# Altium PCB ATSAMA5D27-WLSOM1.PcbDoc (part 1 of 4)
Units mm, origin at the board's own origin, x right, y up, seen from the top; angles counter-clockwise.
Board outline 40.8 x 40.8 mm, 6 copper layers (L1 - Top, L2 - GND, L3 - Signal, L4 - Signal, L5 - PWR, L6 - Bottom), stack 1.144 mm thick; 196 components, 221 nets, 1038 pads, 713 vias.
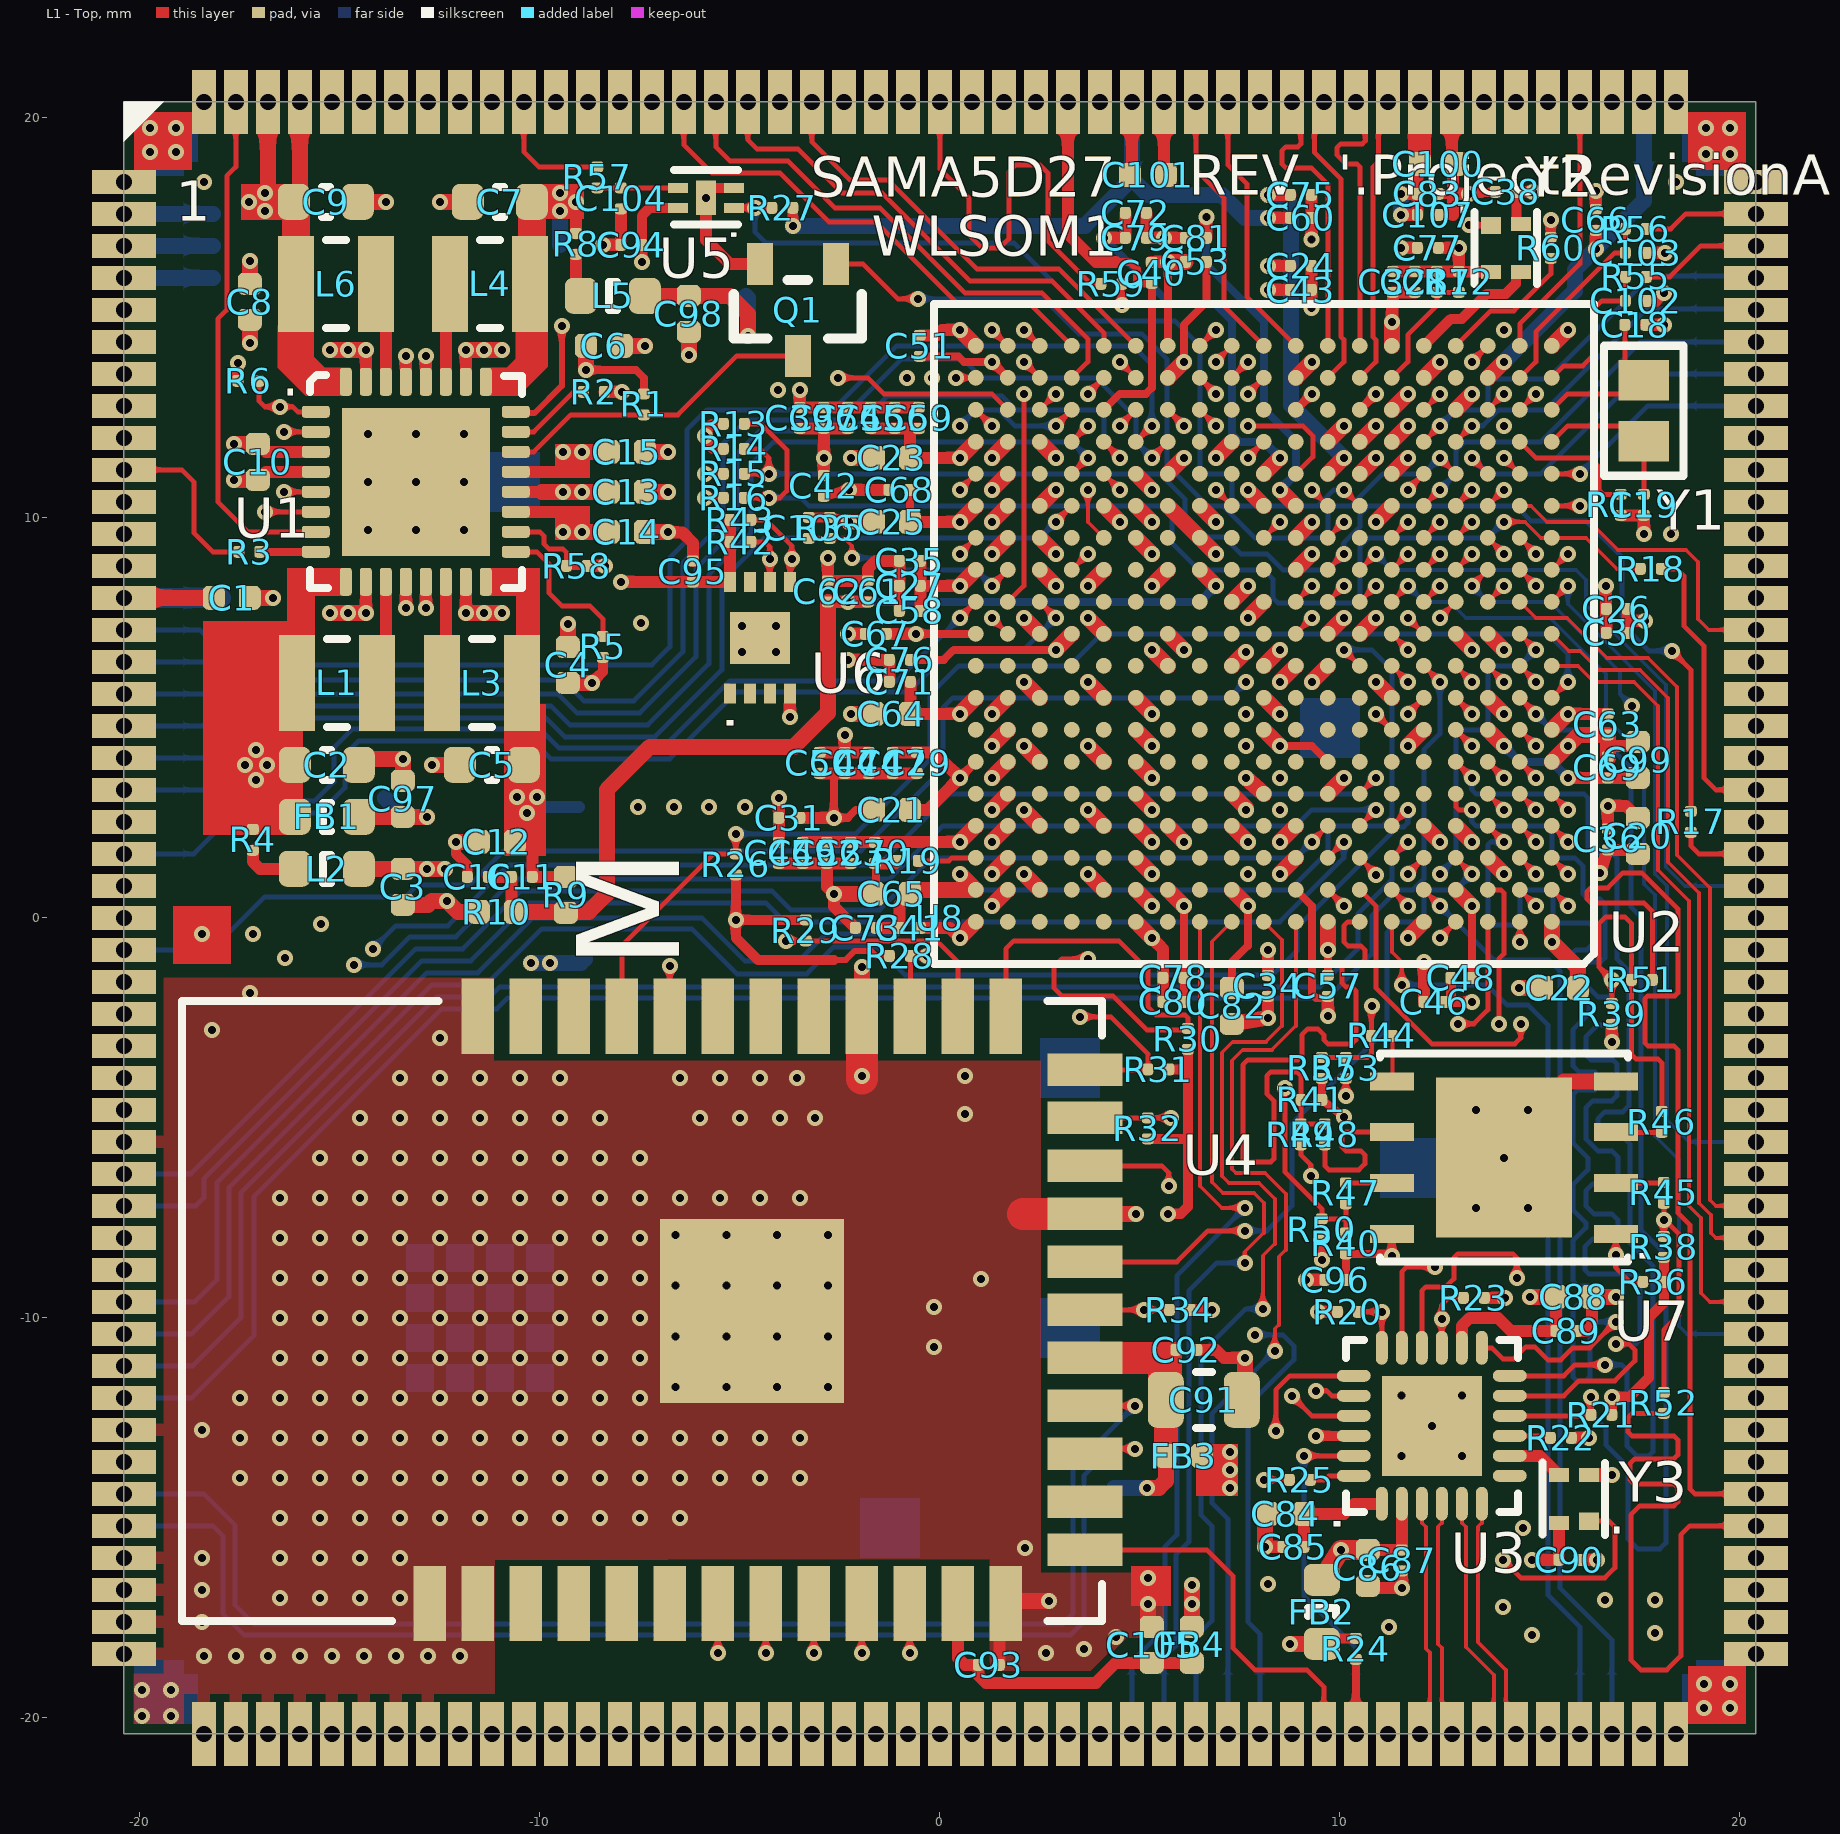
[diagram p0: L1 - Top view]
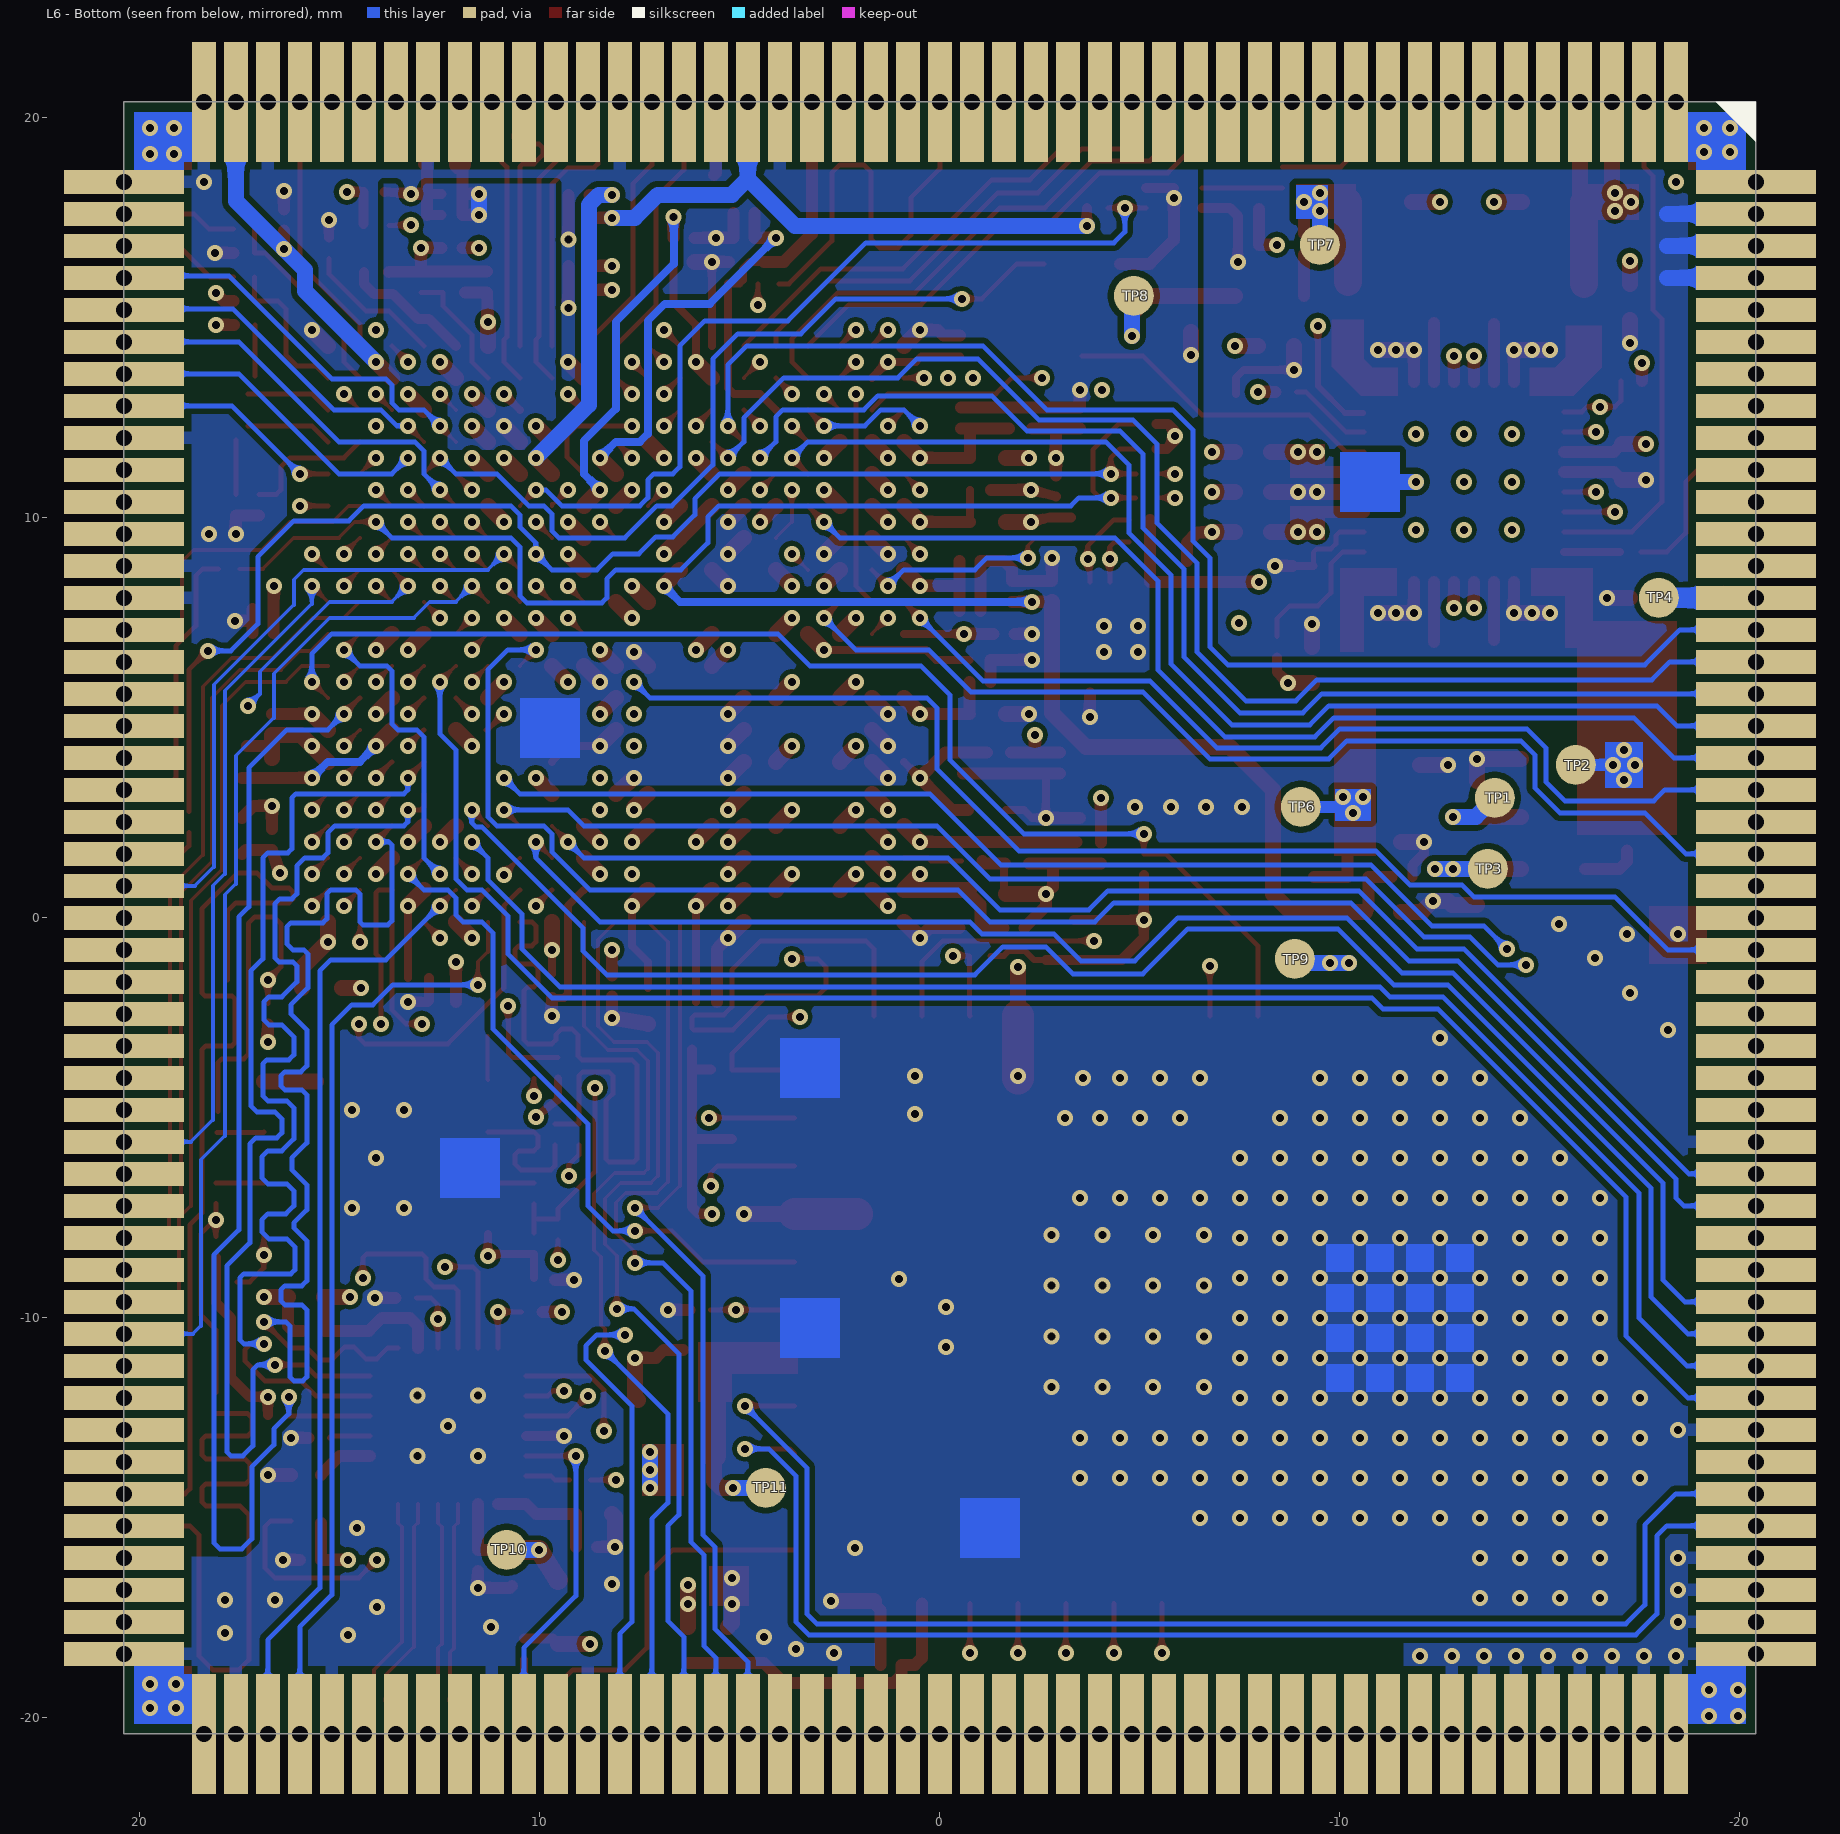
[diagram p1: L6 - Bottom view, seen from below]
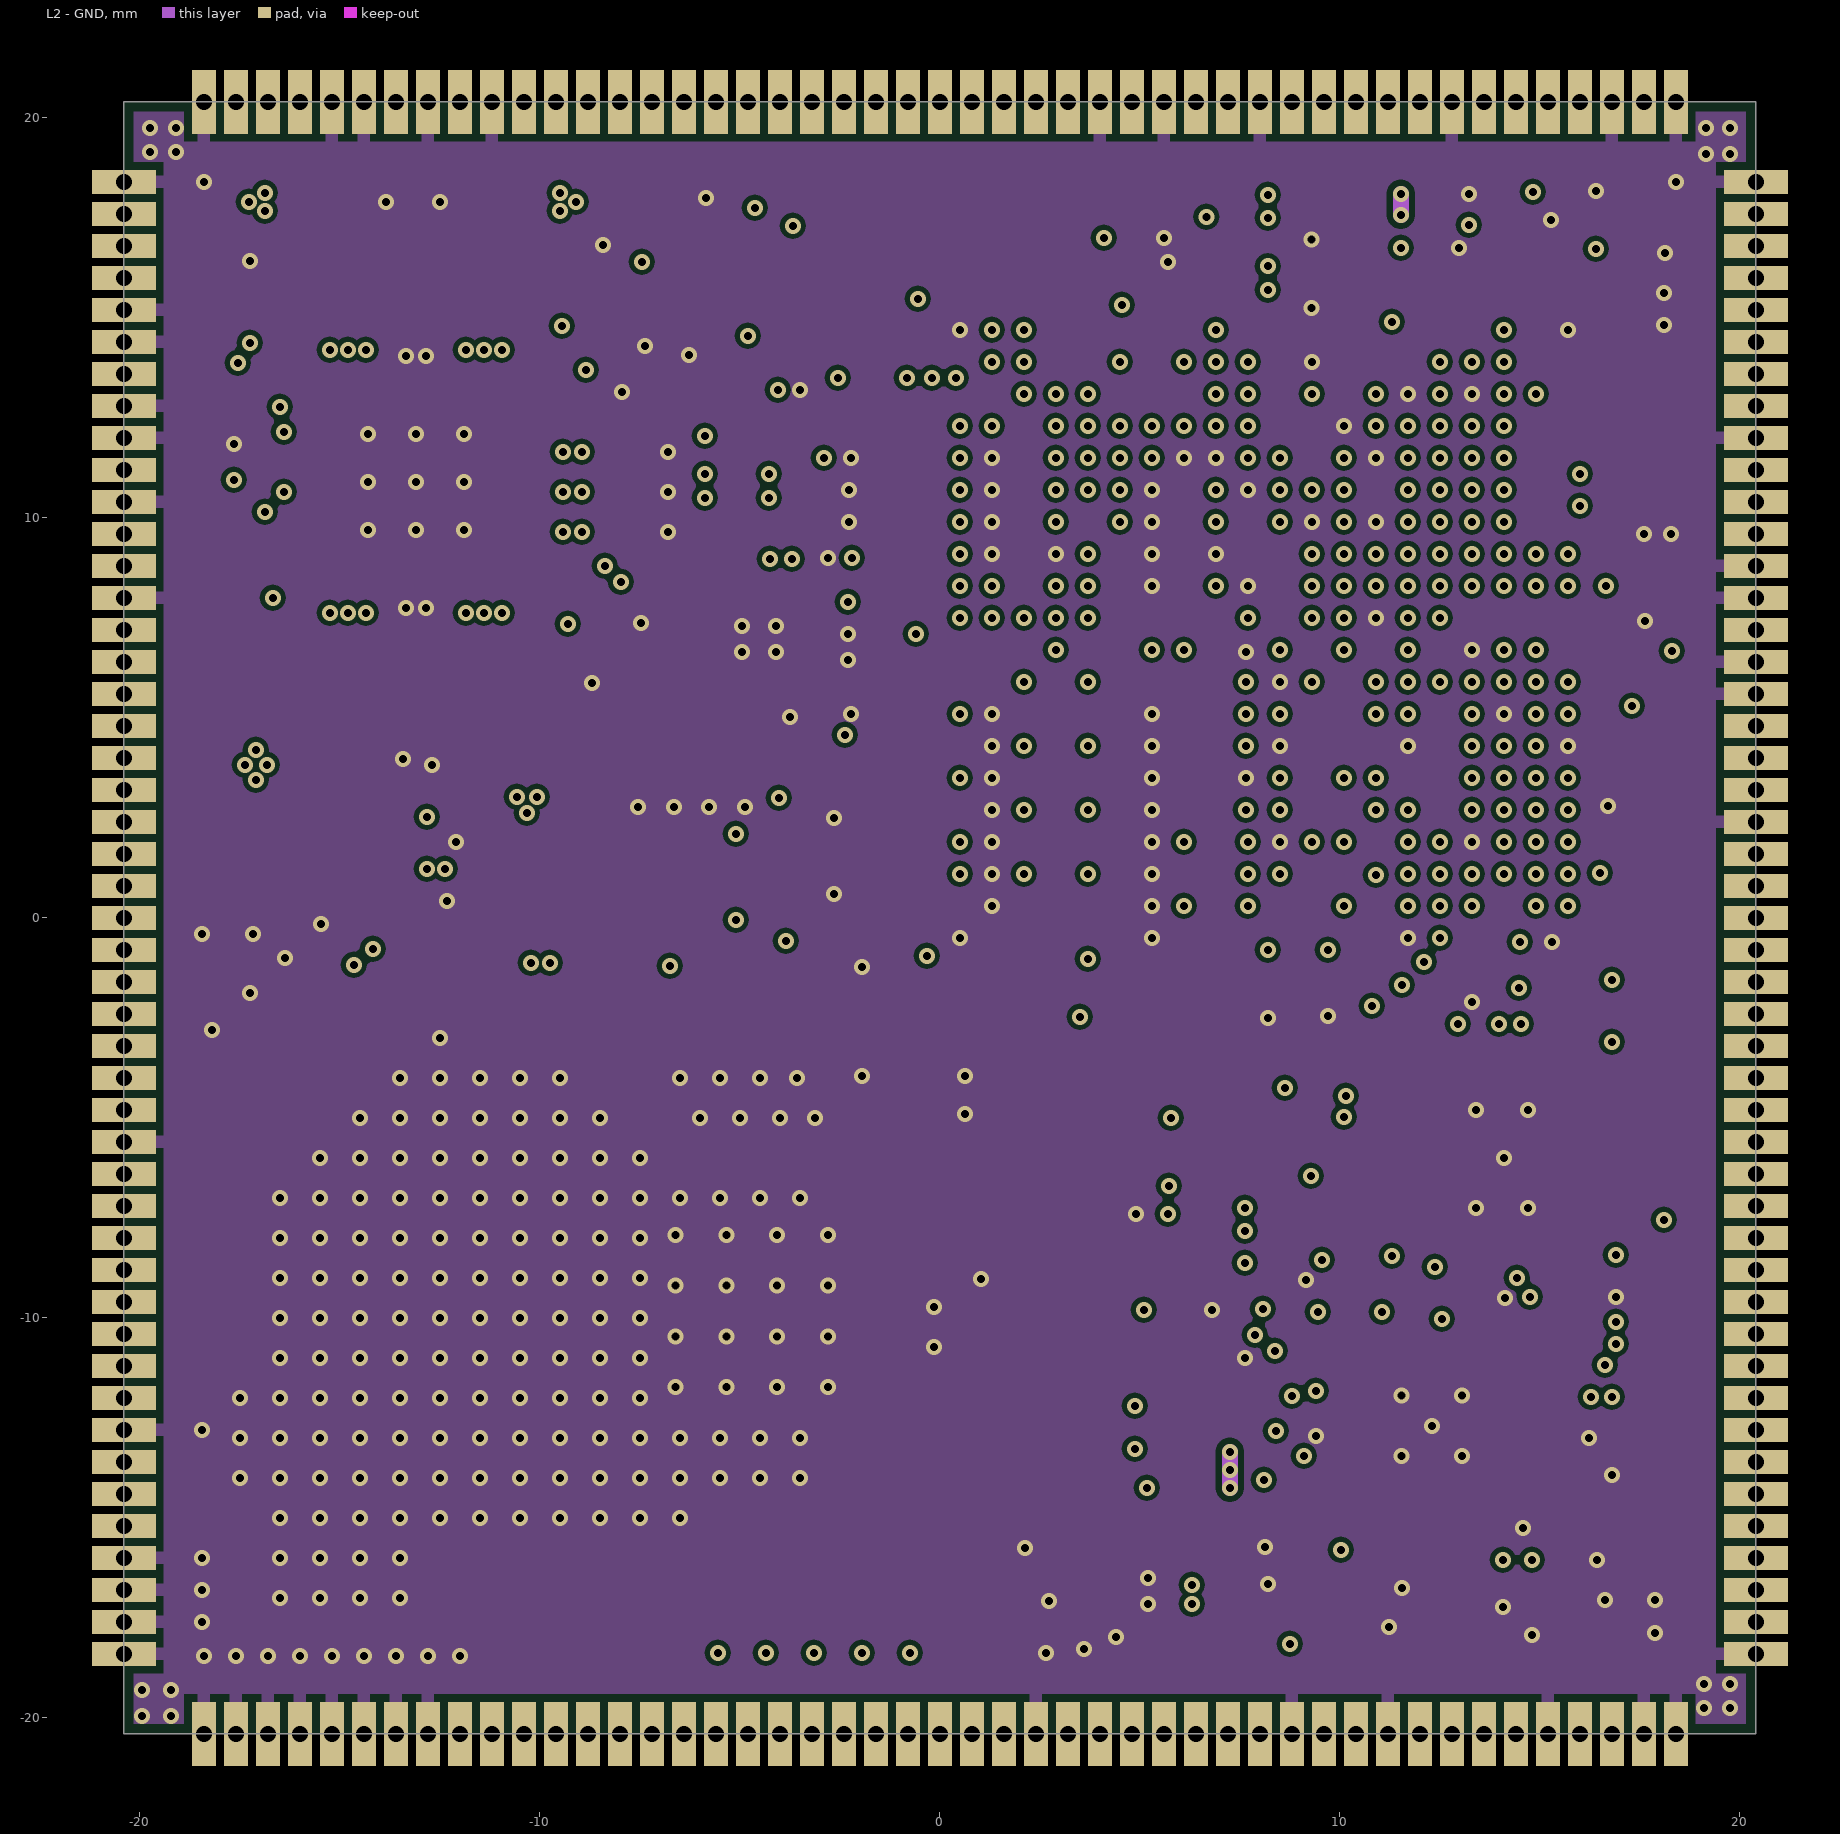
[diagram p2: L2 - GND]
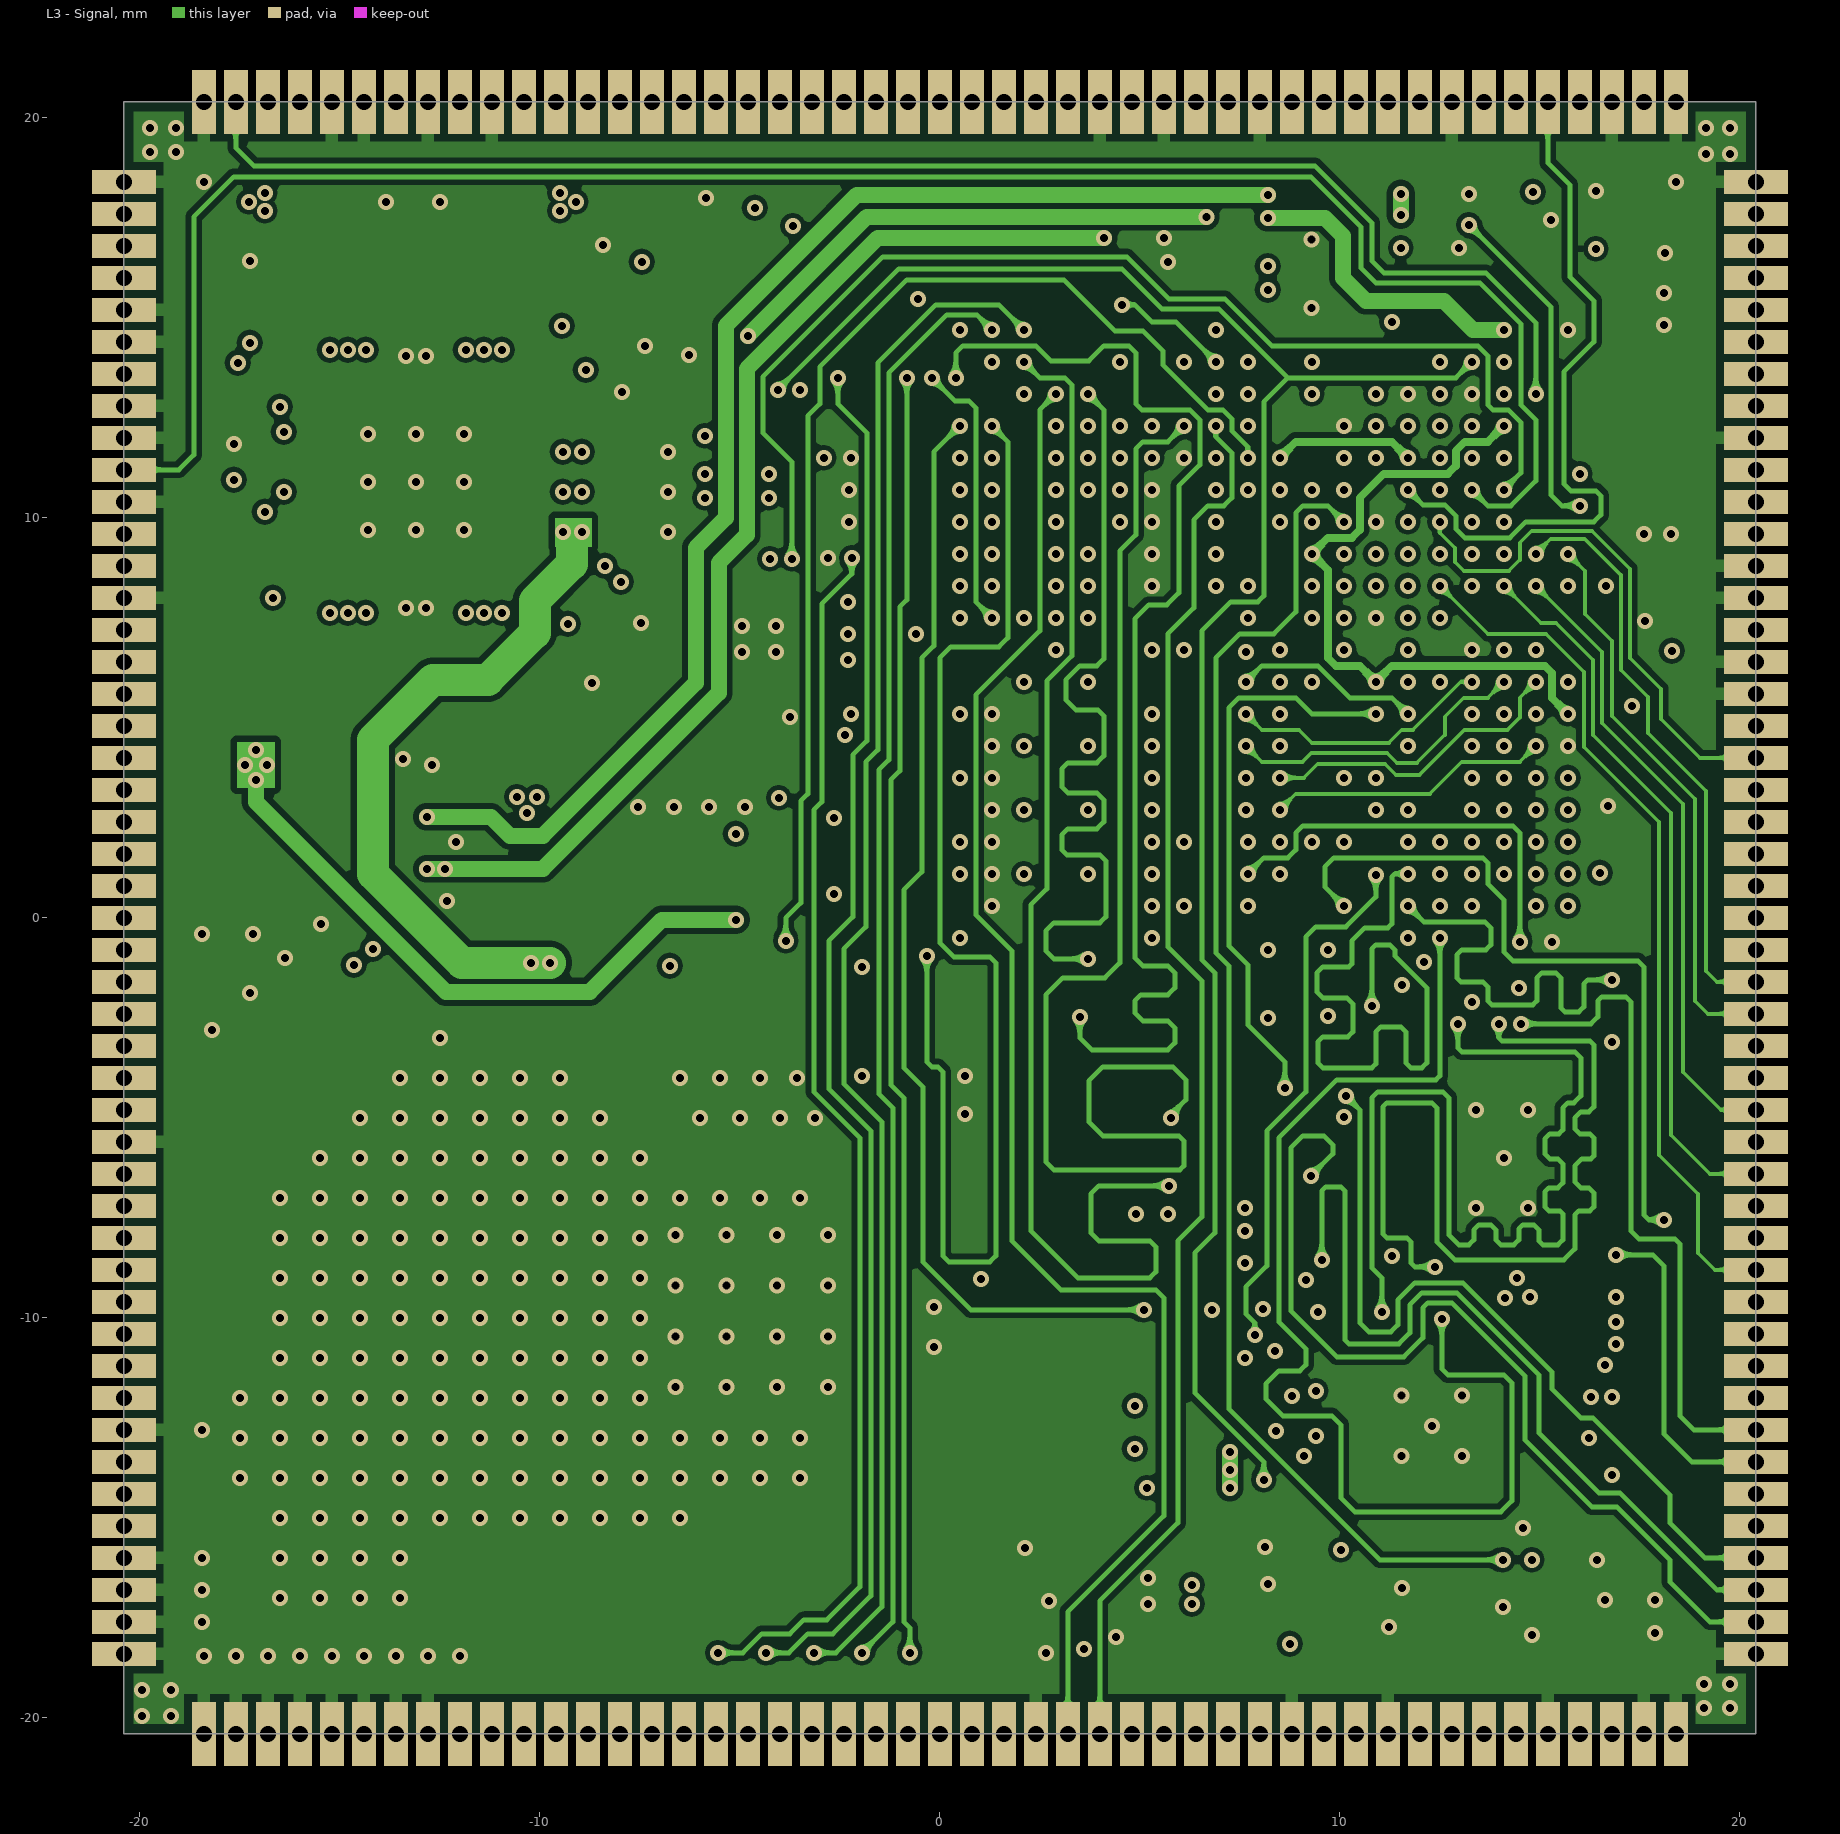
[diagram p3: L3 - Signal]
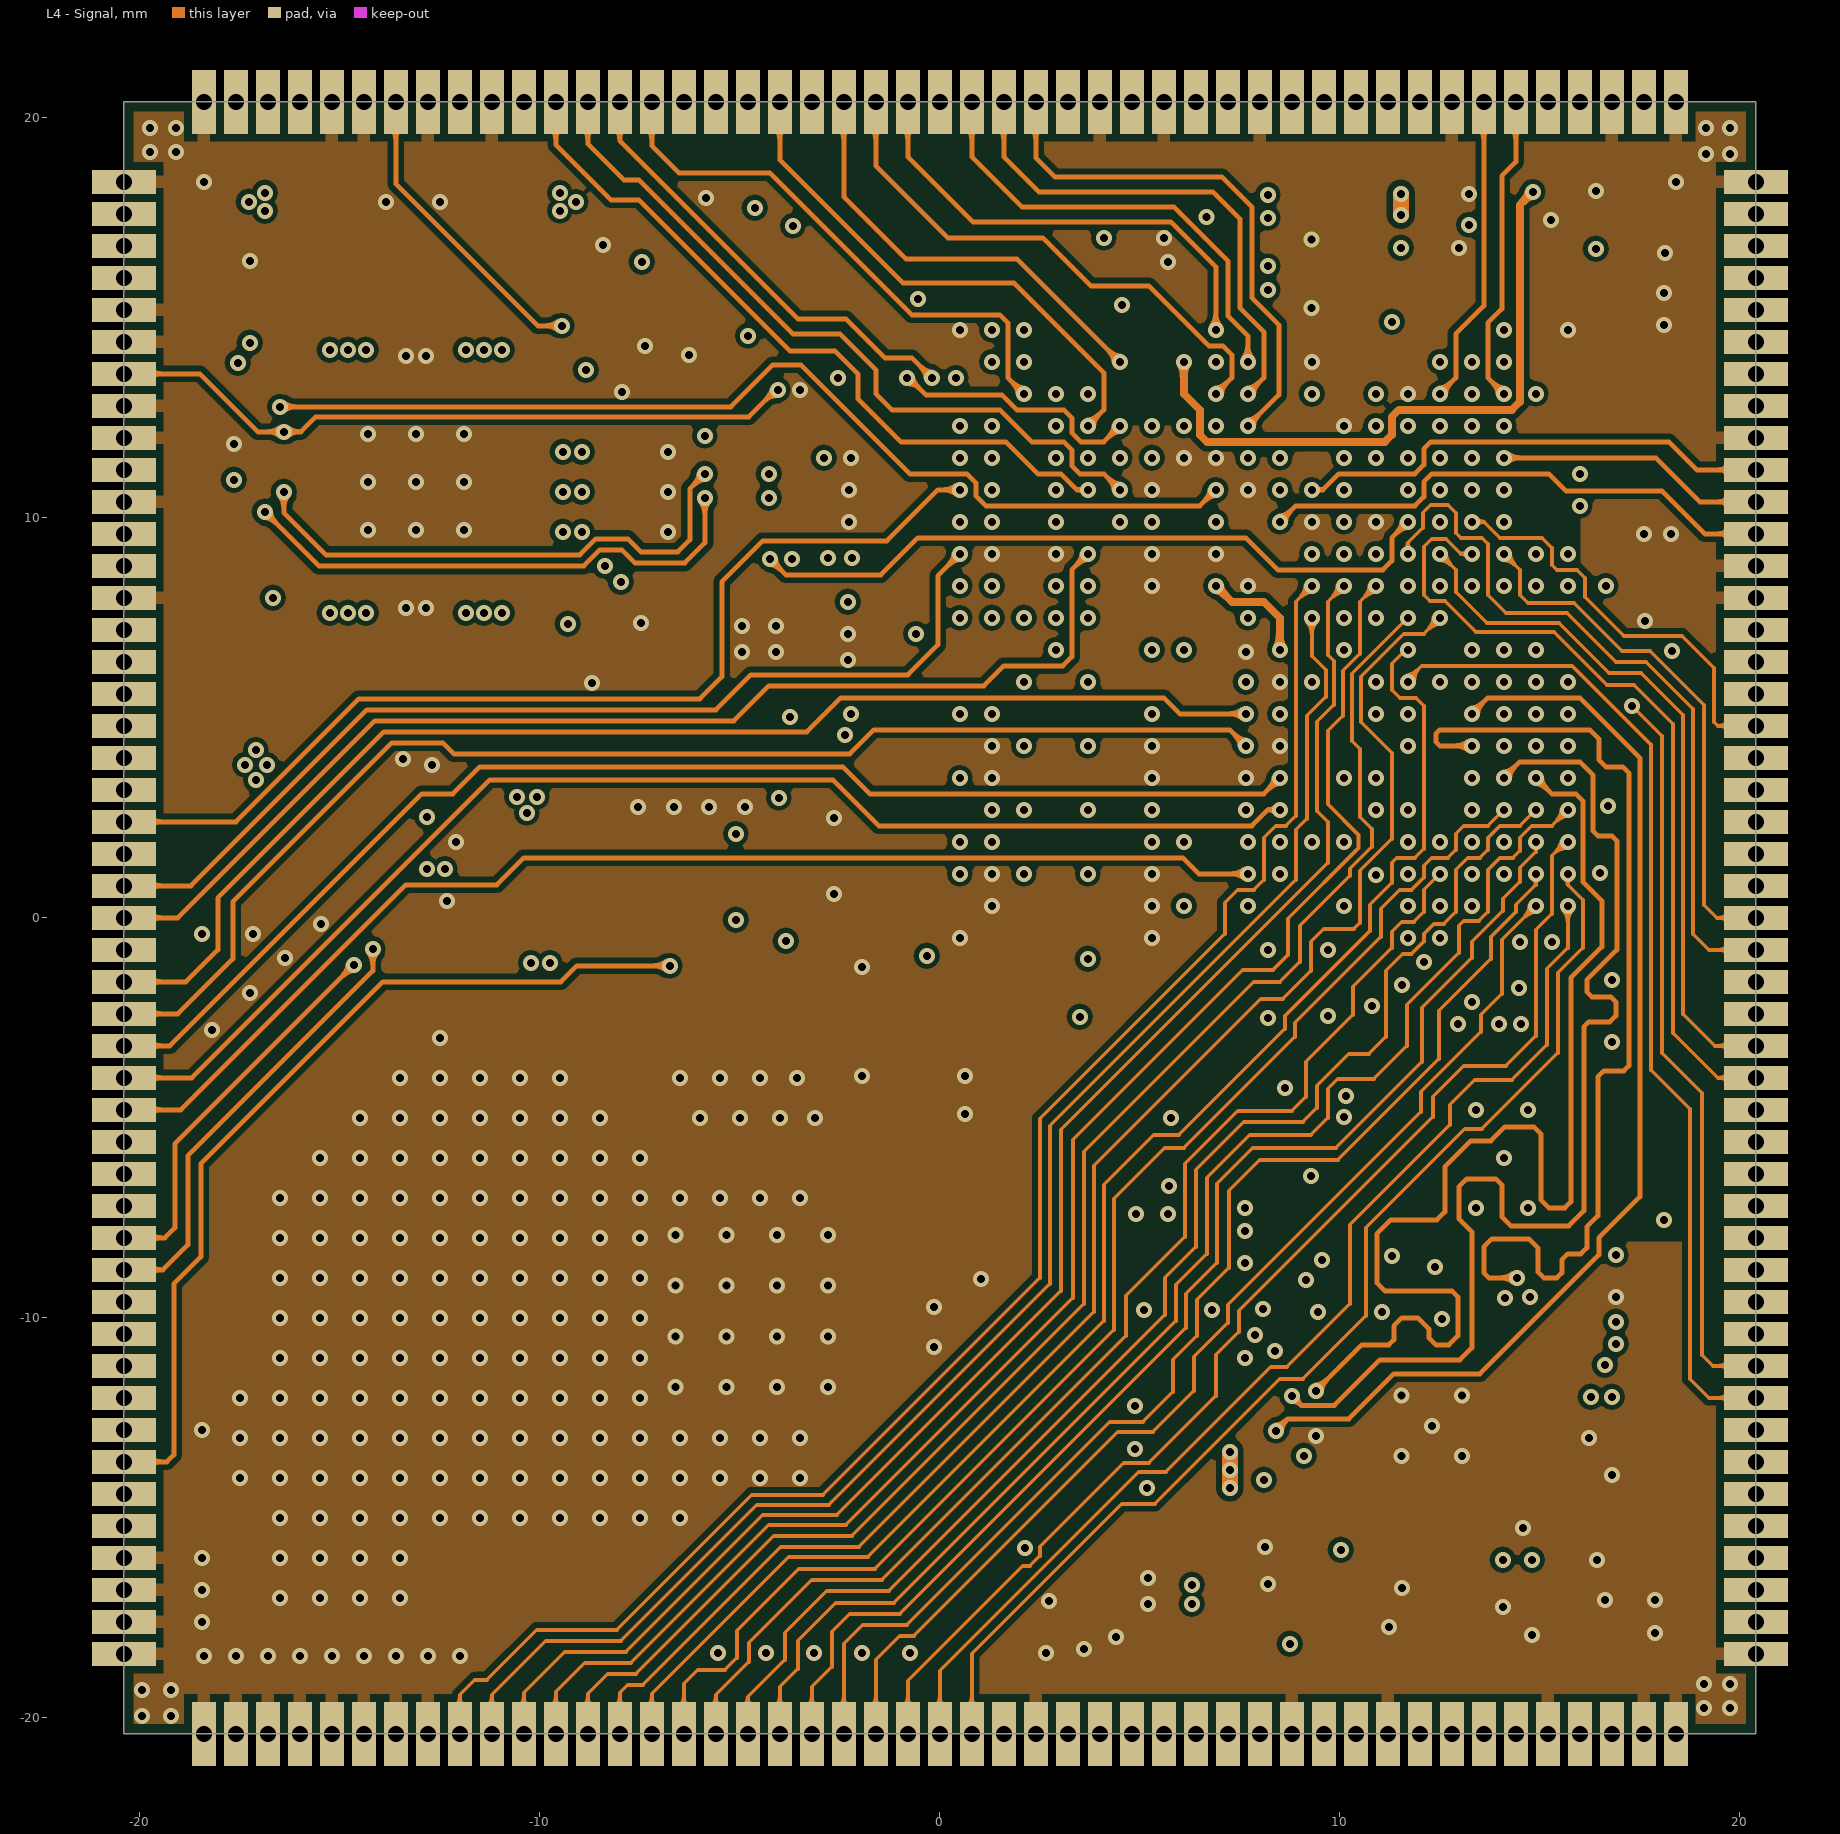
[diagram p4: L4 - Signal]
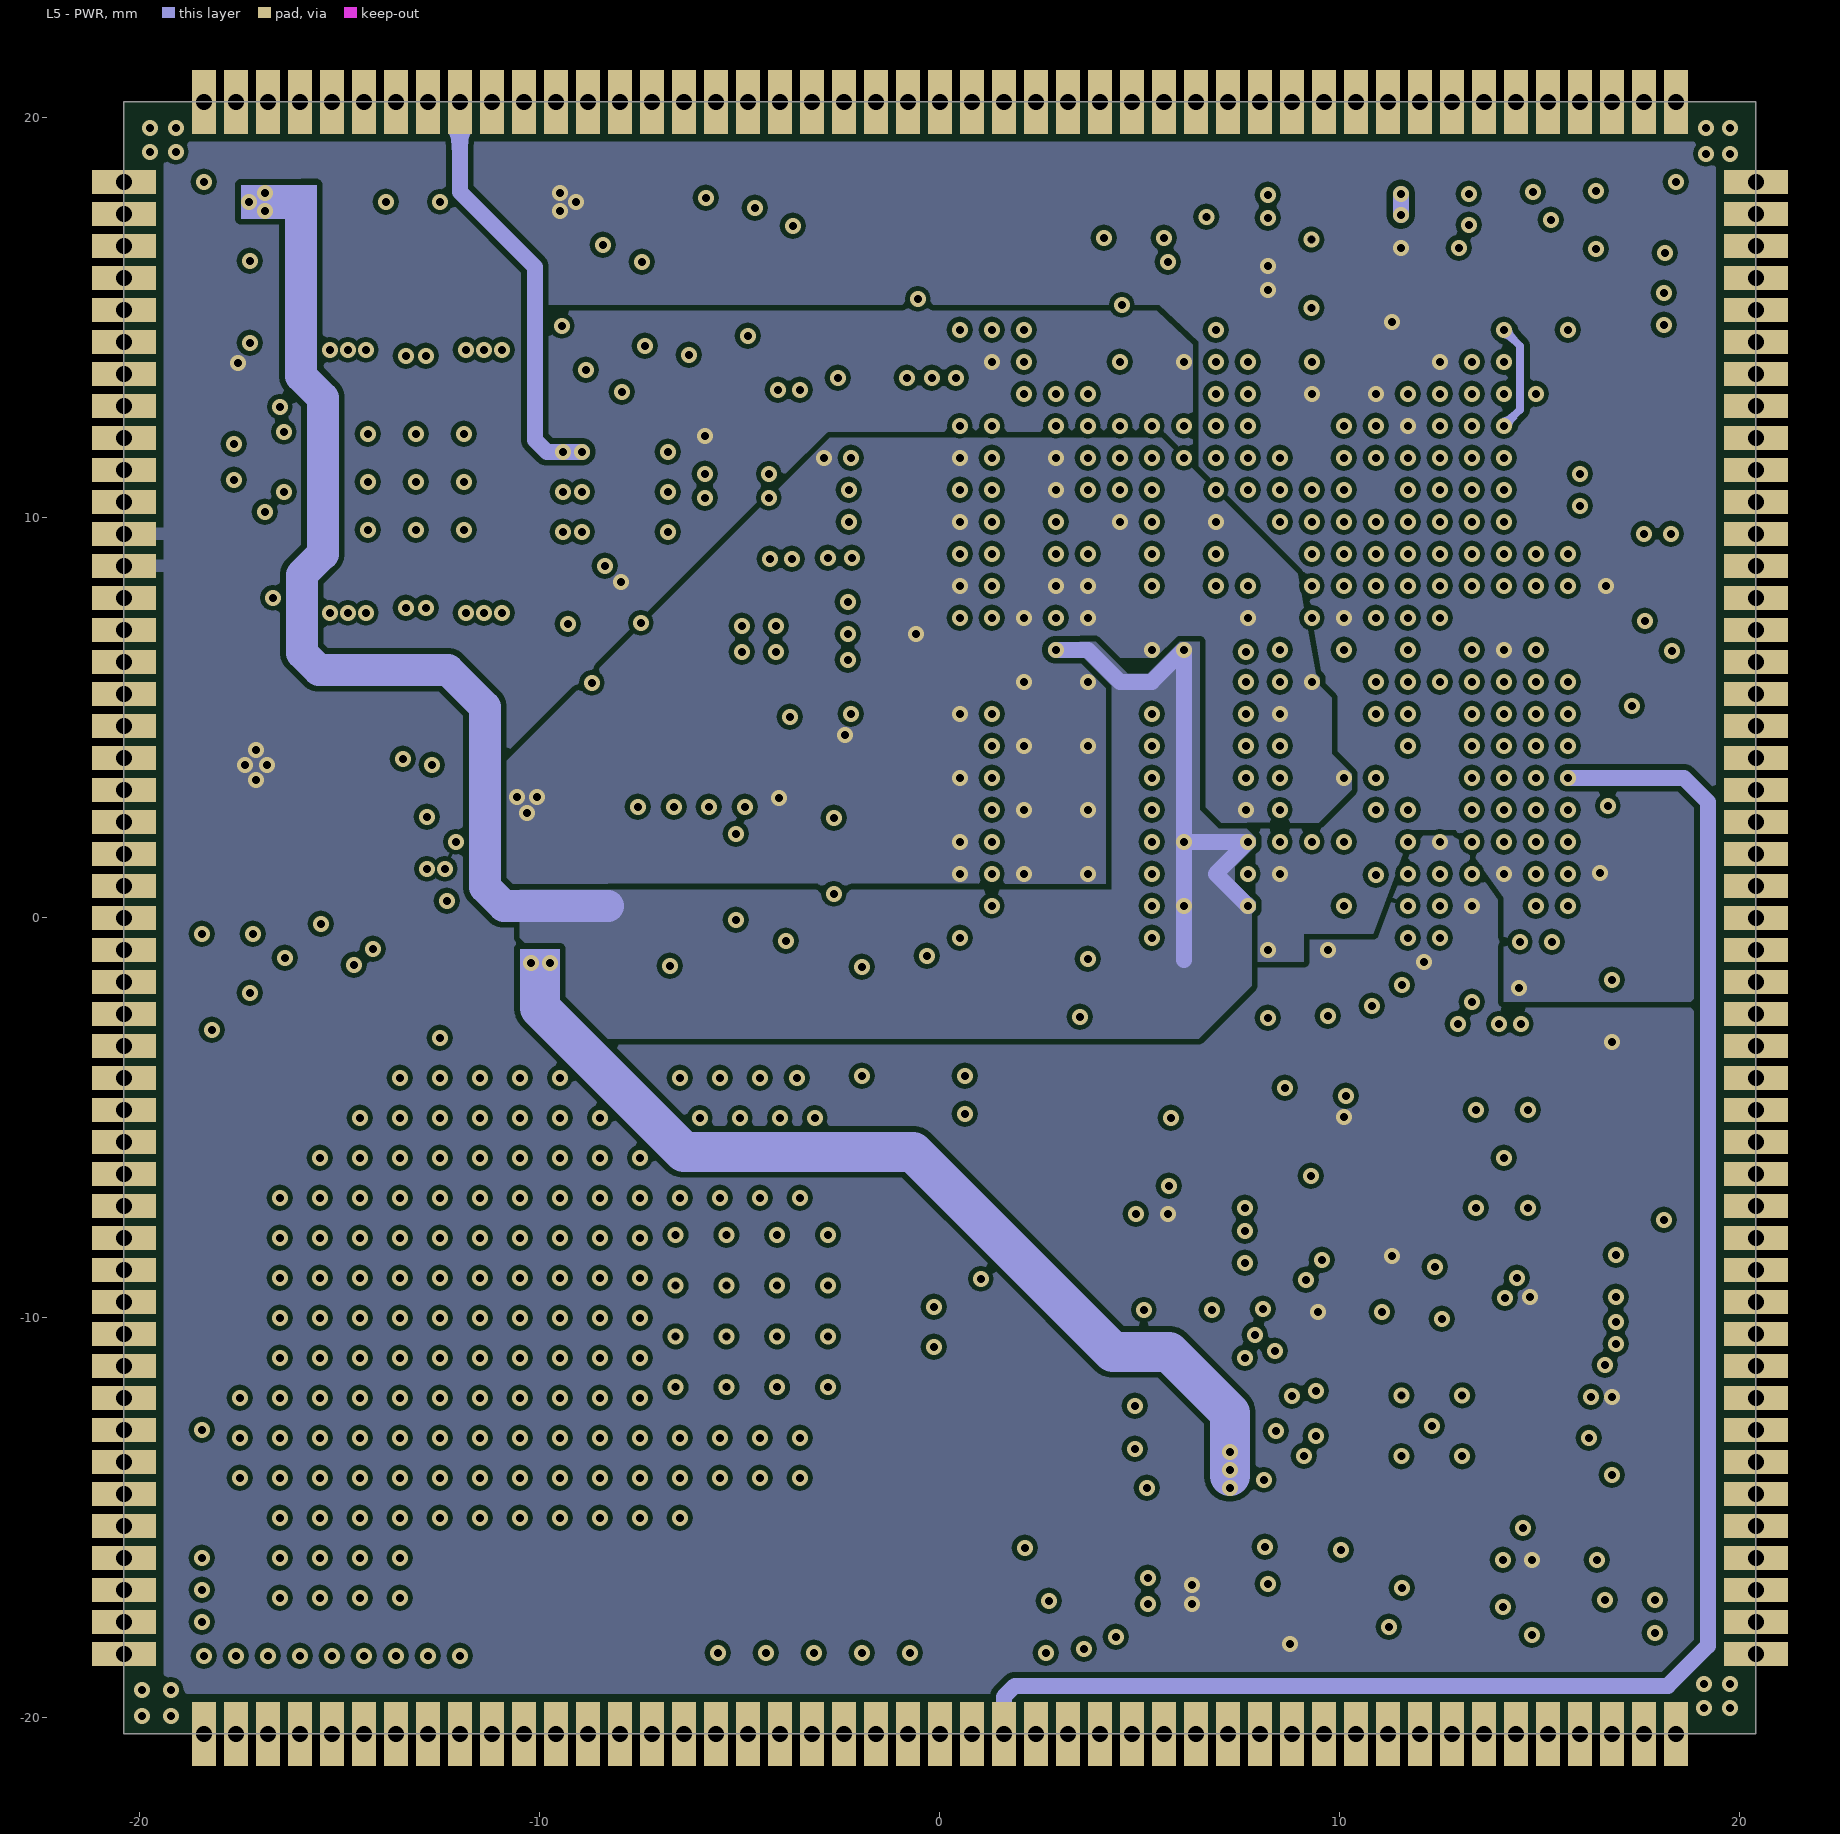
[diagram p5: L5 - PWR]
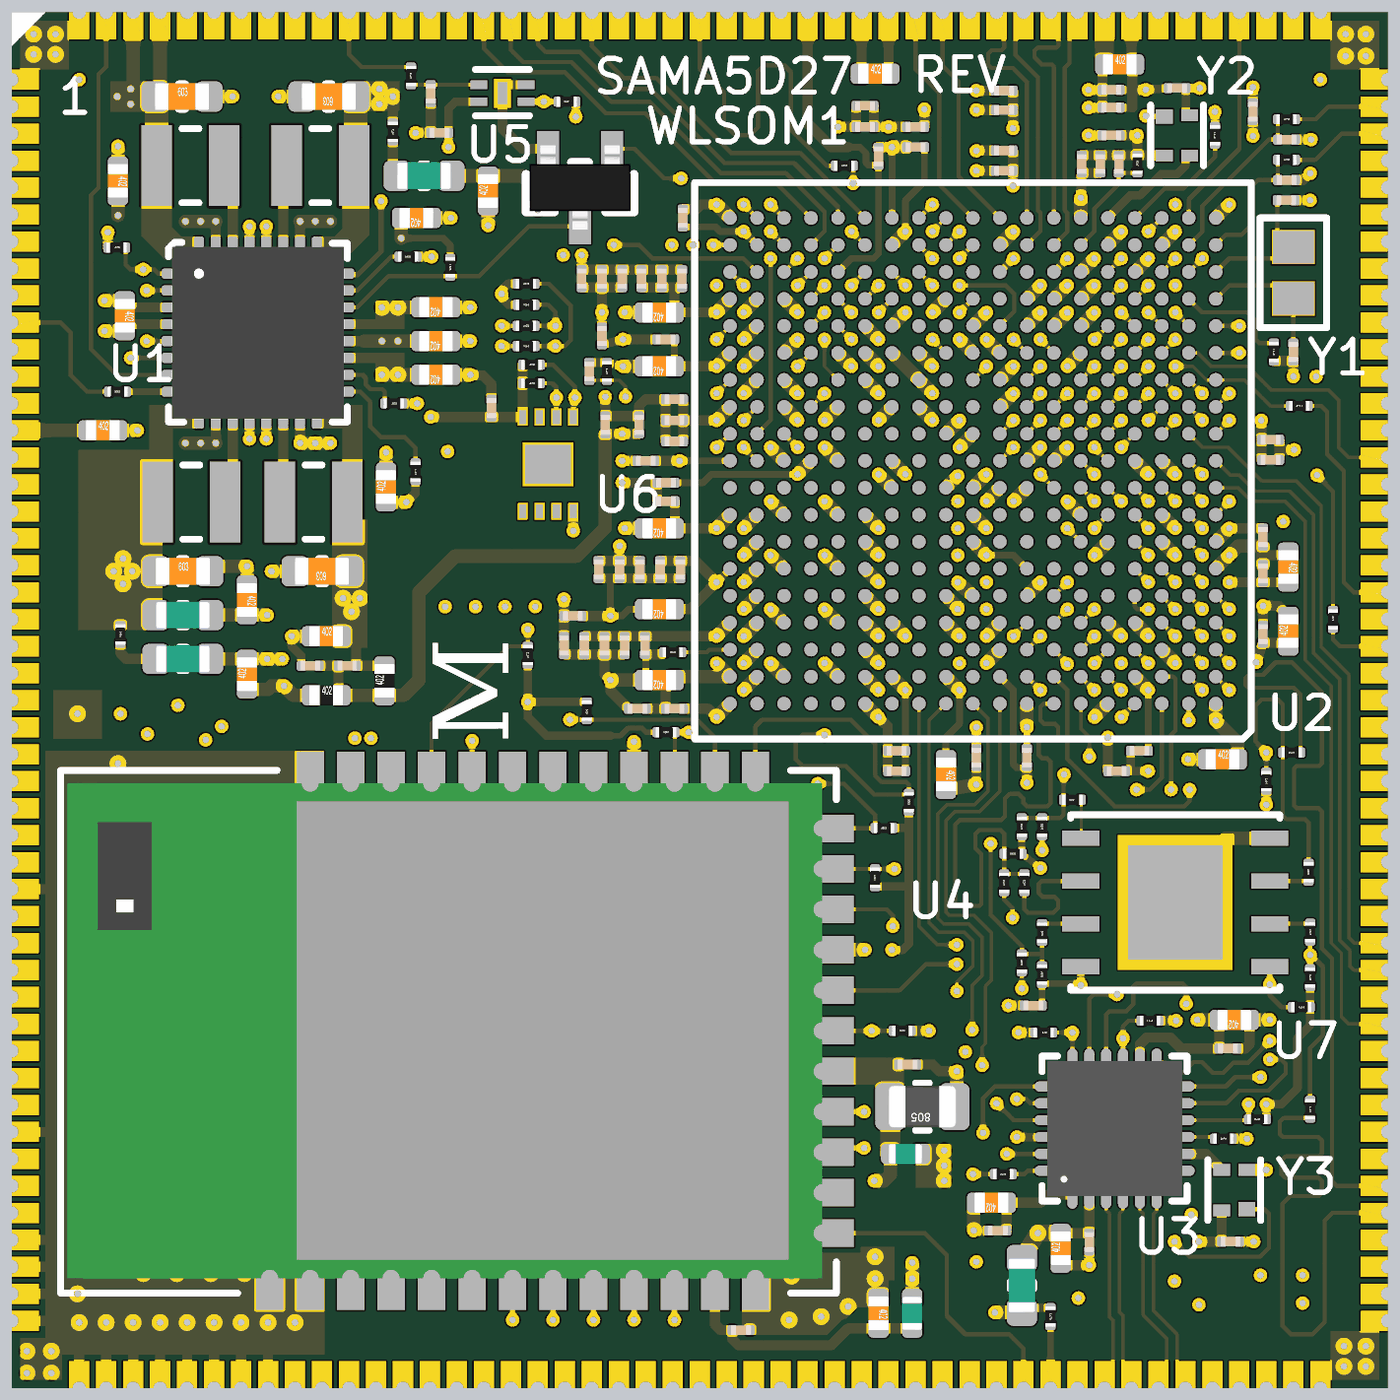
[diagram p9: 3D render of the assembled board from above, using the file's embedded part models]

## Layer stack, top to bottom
Top Solder: solder mask 0.025, Solder Resist, Dk 4
L1 - Top: signal copper 0.035
Dielectric 1: prepreg 0.09, 1 x 3313, Dk 4.2
L2 - GND: signal copper 0.035
Dielectric 2: core 0.127, FR-4, Dk 4.2
L3 - Signal: signal copper 0.035
Dielectric 3: prepreg 0.5, 2 x 7628 + 2 x 1080, Dk 4.2
L4 - Signal: signal copper 0.035
Dielectric 4: core 0.127, FR-4, Dk 4.2
L5 - PWR: signal copper 0.035
Dielectric 5: prepreg 0.09, 1 x 3313, Dk 4.2
L6 - Bottom: signal copper 0.035
Bottom Solder: solder mask 0.025, Solder Resist, Dk 4

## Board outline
-20.4,-20.4 -20.4,20.4 20.4,20.4 20.4,-20.4

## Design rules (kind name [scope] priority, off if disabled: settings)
AssemblyTestPointUsage [All] p1 off:
AssemblyTestpoint [All] p1 off: testpointundercomponent=TRUE minsize=1.016 maxsize=2.54 preferedsize=1.524 minholesize=0 maxholesize=1.016 preferedholesize=0.813 testpointgrid=0.025 usegrid=TRUE gridtolerance=0 allowsidetop=TRUE allowsidebottom=TRUE
BoardOutlineClearance [All] p1: gap=0.25 ignorepadtopadclearanceinfootprint=FALSE
Clearance [All] p1: gap=0.15 ignorepadtopadclearanceinfootprint=TRUE except(0.1: Arc-Arc Arc-Track Arc-SMDPad Arc-THPad Arc-Via Track-Track Track-SMDPad Track-THPad Track-Via; 0.12: Via-Fill Via-Poly Via-Region; 0.125: SMDPad-Via Via-Via; 0.2: THPad-Fill THPad-Poly THPad-Region)
ComponentClearance SOM [InComponent('U8')] p1: gap=0 collisioncheckmode=3 verticalgap=0 showdistances=TRUE
ComponentClearance [All] p2: gap=0.2 collisioncheckmode=3 verticalgap=0.2 showdistances=TRUE
DiffPairsRouting DIFF90 [InDifferentialPairClass('DIFF90')] p1: maxlimit=0.2 minlimit=0.2 mostfreqgap=0.2 toplayer_minwidth=0.125 toplayer_maxwidth=0.125 toplayer_prefwidth=0.125 midlayer1_minwidth=0.125 midlayer1_maxwidth=0.125 midlayer1_prefwidth=0.125 midlayer2_minwidth=0.125 midlayer2_maxwidth=0.125 midlayer2_prefwidth=0.125 midlayer3_minwidth=0.125 midlayer3_maxwidth=0.125 midlayer3_prefwidth=0.125 midlayer4_minwidth=0.125 midlayer4_maxwidth=0.125 midlayer4_prefwidth=0.125 bottomlayer_minwidth=0.125 bottomlayer_maxwidth=0.125 bottomlayer_prefwidth=0.125 maxuncoupledlength=12.7 // 90 ohm differential impedance
DiffPairsRouting DIFF100 [InDifferentialPairClass('DIFF100')] p2: maxlimit=0.2 minlimit=0.2 mostfreqgap=0.2 toplayer_minwidth=0.1 toplayer_maxwidth=0.1 toplayer_prefwidth=0.1 midlayer1_minwidth=0.1 midlayer1_maxwidth=0.1 midlayer1_prefwidth=0.1 midlayer2_minwidth=0.1 midlayer2_maxwidth=0.1 midlayer2_prefwidth=0.1 midlayer3_minwidth=0.1 midlayer3_maxwidth=0.1 midlayer3_prefwidth=0.1 midlayer4_minwidth=0.1 midlayer4_maxwidth=0.1 midlayer4_prefwidth=0.1 bottomlayer_minwidth=0.1 bottomlayer_maxwidth=0.1 bottomlayer_prefwidth=0.1 maxuncoupledlength=12.7 // 100 ohm differential impedance
DiffPairsRouting [All] p3: maxlimit=0.2 minlimit=0.2 mostfreqgap=0.2 toplayer_minwidth=0.1 toplayer_maxwidth=0.1 toplayer_prefwidth=0.1 midlayer1_minwidth=0.1 midlayer1_maxwidth=0.1 midlayer1_prefwidth=0.1 midlayer2_minwidth=0.1 midlayer2_maxwidth=0.1 midlayer2_prefwidth=0.1 midlayer3_minwidth=0.1 midlayer3_maxwidth=0.1 midlayer3_prefwidth=0.1 midlayer4_minwidth=0.1 midlayer4_maxwidth=0.1 midlayer4_prefwidth=0.1 bottomlayer_minwidth=0.1 bottomlayer_maxwidth=0.1 bottomlayer_prefwidth=0.1 maxuncoupledlength=12.7
FabricationTestPointUsage TestPointUsage [All] p1 off: valid=0 allowmultiple=FALSE
FabricationTestpoint Testpoint [All] p1 off: side=3 testpointundercomponent=TRUE minsize=1.016 maxsize=2.54 preferedsize=1.524 minholesize=0 maxholesize=1.016 preferedholesize=0.813 testpointgrid=0.025 allowsidetop=TRUE allowsidebottom=TRUE usegrid=TRUE gridtolerance=0
FanoutControl Fanout_BGA [IsBGA] p1 off: bgadir=Out bgaviamode=Centered fanoutstyle=Auto fanoutdirection=Alternating viagrid=0.025 // Fanout_BGA (Default Rule)
FanoutControl Fanout_LCC [IsLCC] p2 off: bgadir=Out bgaviamode=Centered fanoutstyle=Auto fanoutdirection=Alternating viagrid=0.025 // Fanout_LCC (Default Rule)
FanoutControl Fanout_SOIC [IsSOIC] p3 off: bgadir=Out bgaviamode=Centered fanoutstyle=Auto fanoutdirection=Alternating viagrid=0.025 // Fanout_SOIC (Default Rule)
FanoutControl Fanout_Small [(CompPinCount < 5)] p4 off: bgadir=Out bgaviamode=Centered fanoutstyle=Auto fanoutdirection=OutThenIn viagrid=0.025 // Fanout_Small (Default Rule)
FanoutControl Fanout_Default [All] p5 off: bgadir=Out bgaviamode=Centered fanoutstyle=Auto fanoutdirection=Alternating viagrid=0.025 // Fanout_Default (Default Rule)
HoleSize [All] p1: absolutevalues=TRUE maxlimit=6 minlimit=0.15 maxpercent=80.000 minpercent=20.000
HoleToHoleClearance [All] p1: gap=0.25 allowstackedmicrovias=FALSE
MatchedLengths HSIC [InNetClass('HSIC')] p1: tolerance=0.05 checknetsindiffpair=FALSE checkdiffpairvsdiffpair=TRUE checkxsignals=TRUE checkothers=TRUE
MatchedLengths SD-IO [InNetClass('SDIO')] p2: tolerance=0.25 checknetsindiffpair=FALSE checkdiffpairvsdiffpair=TRUE checkxsignals=TRUE checkothers=TRUE
MatchedLengths Q-SPI [InNetClass('QSPI')] p3 off: tolerance=0.25 checknetsindiffpair=FALSE checkdiffpairvsdiffpair=TRUE checkxsignals=TRUE checkothers=TRUE
MatchedLengths DIFF-100 [InNetClass('DIFF100')] p4: tolerance=0.1 checknetsindiffpair=TRUE checkdiffpairvsdiffpair=FALSE checkxsignals=FALSE checkothers=FALSE
MatchedLengths DIFF-90 [InNetClass('DIFF90')] p5: tolerance=0.1 checknetsindiffpair=TRUE checkdiffpairvsdiffpair=FALSE checkxsignals=FALSE checkothers=FALSE
MatchedLengths ETH_PHY [InNetClass('ETH-PHY')] p6 off: tolerance=0.25 checknetsindiffpair=FALSE checkdiffpairvsdiffpair=TRUE checkxsignals=TRUE checkothers=TRUE
MinimumAnnularRing [All] p1: minimumring=0.1
MinimumSolderMaskSliver [All] p1: minsoldermaskwidth=0.1
PasteMaskExpansion "Remove Paste from DNP" [IsPad and HasCompParameterValue('Populated','DNP')] p1: expansion=-10
PasteMaskExpansion [All] p2: expansion=0
PlaneClearance [All] p1 off: clearance=0.508
PlaneConnect [All] p1 off: planeconnectstyle=Relief reliefexpansion=0.508 reliefentries=4 reliefconductorwidth=0.254 reliefairgap=0.254
PolygonConnect [All] p1: thpad.connectstyle=Relief thpad.reliefconductorwidth=0.3 thpad.reliefentries=4 thpad.polygonreliefangle="90 Angle" thpad.airgapwidth=0.2 smdpad.connectstyle=Direct smdpad.reliefconductorwidth=0.4 smdpad.reliefentries=4 smdpad.polygonreliefangle="90 Angle" smdpad.airgapwidth=0.2 via.connectstyle=Direct via.reliefconductorwidth=0.3 via.reliefentries=4 via.polygonreliefangle="90 Angle" via.airgapwidth=0.2
RoutingCorners [All] p1: cornerstyle=45-Degree minsetback=2.5 maxsetback=2.5
RoutingVias [All] p1: holewidth=0.2 width=0.4 viastyle="Through Hole" minholewidth=0.2 minwidth=0.4 maxholewidth=0.2 maxwidth=0.4
SilkToSilkClearance [All] p1: silktosilkclearance=0.15
SilkToSolderMaskClearance SilkscreenOverComponentPads [IsPad] p1: minsilkscreentomaskgap=0.15 clearancetoexposedcopper=TRUE
SolderMaskExpansion SolderMaskExpansion_Via [IsVia] p1: expansion=-1
SolderMaskExpansion SolderMaskExpansion_All [All] p2: expansion=0.05
Width [All] p1: maxlimit=2 minlimit=0.1 preferedwidth=0.2
10 further rules are at their usual default settings.

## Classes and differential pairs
net class SDMMC0: PA0 PA1 PA2 PA3 PA4 PA5 PA6 PA7 PA8 PA9
net class HSIC: HSIC_DATA HSIC_STROBE
net class SDIO: SDIO_CLK_WILC_PA22 SDIO_CMD_WILC_PA28 SDIO_DAT0_WILC_PA18 SDIO_DAT1_WILC_PA19 SDIO_DAT2_WILC_PA20 SDIO_DAT3_WILC_PA21
net class QSPI: QSPI1_IO0_PB7 QSPI1_IO1_PB8 QSPI1_IO2_PB9 QSPI1_IO3_PB10 QSPI1_SCK_PB5
differential pair class DIFF100: ETH_RX ETH_TX
differential pair class DIFF90: USBA USBB
net class ETH-PHY: ETH_GMDC_PB22 ETH_GMDIO_PB23 ETH_GRX0_PB18 ETH_GRX1_PB19 ETH_GRXDV_PB16 ETH_GRXER_PB17 ETH_GTX0_PB20 ETH_GTX1_PB21 ETH_GTXCK_PB14 ETH_GTXEN_PB15 ETH_INT_PB24
net class DIFF100: ETH_RX_N ETH_RX_P ETH_TX_N ETH_TX_P
net class DIFF90: USBA_N USBA_P USBB_N USBB_P
differential pair USBB: +USBB_P -USBB_N
differential pair USBA: +USBA_P -USBA_N
differential pair ETH_TX: +ETH_TX_P -ETH_TX_N
differential pair ETH_RX: +ETH_RX_P -ETH_RX_N

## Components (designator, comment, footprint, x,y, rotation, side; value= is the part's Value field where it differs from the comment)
C1 "Capacitor NP" CAP_C_0402 -17.7,8 r0 top value=4.7uF
C2 "Capacitor NP" CAP_C_0603 -15.325,3.825 r0 top value=22uF
C3 "Capacitor NP" CAP_C_0402 -13.425,0.775 r90 top value=4.7uF
C4 "Capacitor NP" CAP_C_0402 -9.3,6.325 r90 top value=4.7uF
C5 "Capacitor NP" CAP_C_0603 -11.2,3.825 r180 top value=22uF
C6 "Capacitor NP" CAP_C_0402 -8.4,14.3 r180 top value=4.7uF
C7 "Capacitor NP" CAP_C_0603 -11,17.9 r180 top value=22uF
C8 "Capacitor NP" CAP_C_0402 -17.25,15.4 r270 top value=4.7uF
C9 "Capacitor NP" CAP_C_0603 -15.35,17.9 r0 top value=22uF
C10 "Capacitor NP" CAP_C_0402 -17.05,11.4 r270 top value=4.7uF
C11 "Capacitor NP" CAP_C_0201 -10.45,1.025 r0 top value=0.1uF
C12 "Capacitor NP" CAP_C_0402 -11.075,1.9 r0 top value=4.7uF
C13 "Capacitor NP" CAP_C_0402 -7.825,10.65 r180 top value=4.7uF
C14 "Capacitor NP" CAP_C_0402 -7.825,9.65 r180 top value=4.7uF
C15 "Capacitor NP" CAP_C_0402 -7.825,11.65 r180 top value=4.7uF
C16 "Capacitor NP" CAP_C_0201 -11.55,1.025 r0 top value=0.1uF
C17 "Capacitor NP" CAP_C_0201 12.425,15.9 r270 top value=10pF
C18 "Capacitor NP" CAP_C_0201 17.387,14.825 r180 top value=8pF
C19 "Capacitor NP" CAP_C_0201 17.6,10.325 r90 top value=8pF
C20 "Capacitor NP" CAP_C_0402 17.45,2.05 r90 top value=4.7uF
C21 "Capacitor NP" CAP_C_0402 -1.2,2.7 r180 top value=4.7uF
C22 "Capacitor NP" CAP_C_0402 15.5,-1.75 r0 top value=4.7uF
C23 "Capacitor NP" CAP_C_0402 -1.2,11.5 r180 top value=4.7uF
C24 "Capacitor NP" CAP_C_0201 9.025,16.3 r0 top value=0.1uF
C25 "Capacitor NP" CAP_C_0402 -1.2,9.9 r180 top value=4.7uF
C26 "Capacitor NP" CAP_C_0201 16.925,7.725 r0 top value=0.1uF
C27 "Capacitor NP" CAP_C_0201 -0.75,8.3 r180 top value=0.1uF
C28 "Capacitor NP" CAP_C_0201 11.875,15.9 r90 top value=0.1uF
C29 "Capacitor NP" CAP_C_0201 -0.575,3.875 r270 top value=0.1uF
C30 "Capacitor NP" CAP_C_0201 16.925,7.125 r0 top value=0.1uF
C31 "Capacitor NP" CAP_C_0201 -3.763,2.5 r0 top value=0.1uF
C32 "Capacitor NP" CAP_C_0201 11.325,15.9 r90 top value=0.1uF
C33 "Capacitor NP" CAP_C_0201 -2.225,1.625 r270 top value=0.1uF
C34 "Capacitor NP" CAP_C_0201 8.2,-1.7 r270 top value=0.1uF
C35 "Capacitor NP" CAP_C_0201 -0.75,8.925 r180 top value=0.1uF
C36 "Capacitor NP" CAP_C_0201 16.7,1.962 r90 top value=0.1uF
C37 "Capacitor NP" CAP_C_0201 -2.9,12.5 r90 top value=0.1uF
C38 "Capacitor NP" CAP_C_0201 14.15,18.15 r0 top value=0.1uF
C39 "Capacitor NP" CAP_C_0201 -3.5,12.5 r90 top value=0.1uF
C40 "Capacitor NP" CAP_C_0201 5.3,16.125 r90 top value=0.1uF
C41 "Capacitor NP" CAP_C_0201 -0.75,-0.25 r0 top value=0.1uF
C42 "Capacitor NP" CAP_C_0201 -2.9,10.8 r270 top value=0.1uF
C43 "Capacitor NP" CAP_C_0201 9.025,15.7 r0 top value=0.1uF
C44 "Capacitor NP" CAP_C_0201 -2.375,3.875 r270 top value=0.1uF
C45 "Capacitor NP" CAP_C_0201 -4.025,1.625 r270 top value=0.1uF
C46 "Capacitor NP" CAP_C_0201 12.363,-2.1 r0 top value=0.1uF
C47 "Capacitor NP" CAP_C_0201 -1.175,3.875 r270 top value=0.1uF
C48 "Capacitor NP" CAP_C_0201 13.037,-1.5 r180 top value=0.1uF
C49 "Capacitor NP" CAP_C_0201 -3.425,1.625 r270 top value=0.1uF
C50 "Capacitor NP" CAP_C_0201 -3,3.875 r270 top value=0.1uF
C51 "Capacitor NP" CAP_C_0201 -0.5,14.3 r90 top value=0.1uF
C52 "Capacitor NP" CAP_C_0201 -2.825,1.625 r270 top value=0.1uF
C53 "Capacitor NP" CAP_C_0201 6.4,16.4 r180 top value=0.1uF
C54 "Capacitor NP" CAP_C_0201 -2.3,12.5 r90 top value=0.1uF
C55 "Capacitor NP" CAP_C_0201 -1.725,12.5 r90 top value=0.1uF
C56 "Capacitor NP" CAP_C_0201 -1.125,12.5 r90 top value=0.1uF
C57 "Capacitor NP" CAP_C_0201 9.7,-1.7 r270 top value=0.1uF
C58 "Capacitor NP" CAP_C_0201 -0.75,7.675 r180 top value=0.1uF
C59 "Capacitor NP" CAP_C_0201 -0.525,12.5 r90 top value=0.1uF
C60 "Capacitor NP" CAP_C_0201 9.025,17.5 r0 top value=0.1uF
C61 "Capacitor NP" CAP_C_0201 -1.8,8.162 r90 top value=0.1uF
C62 "Capacitor NP" CAP_C_0201 -2.8,8.162 r90 top value=0.1uF
C63 "Capacitor NP" CAP_C_0201 16.7,4.838 r270 top value=0.1uF
C64 "Capacitor NP" CAP_C_0402 -1.2,5.1 r180 top value=4.7uF
C65 "Capacitor NP" CAP_C_0402 -1.2,0.6 r180 top value=4.7uF
C66 "Capacitor NP" CAP_C_0201 16.4,17.45 r90 top value=0.1uF
C67 "Capacitor NP" CAP_C_0201 -1.6,7.1 r180 top value=0.1uF
C68 "Capacitor NP" CAP_C_0201 -1.012,10.7 r180 top value=0.1uF
C69 "Capacitor NP" CAP_C_0201 16.7,3.762 r90 top value=0.1uF
C70 "Capacitor NP" CAP_C_0201 -1.625,1.625 r270 top value=0.1uF
C71 "Capacitor NP" CAP_C_0201 -1,5.9 r180 top value=0.1uF
C72 "Capacitor NP" CAP_C_0201 4.9,17.625 r0 top value=0.1uF
C73 "Capacitor NP" CAP_C_0201 -1.85,-0.25 r180 top value=0.1uF
C74 "Capacitor NP" CAP_C_0201 -1.775,3.875 r270 top value=0.1uF
C75 "Capacitor NP" CAP_C_0201 9.025,18.075 r0 top value=0.1uF
C76 "Capacitor NP" CAP_C_0201 -1,6.45 r180 top value=0.1uF
C77 "Capacitor NP" CAP_C_0201 12.2,16.75 r0 top value=0.1uF
C78 "Capacitor NP" CAP_C_0201 5.838,-1.5 r180 top value=0.1uF
C79 "Capacitor NP" CAP_C_0201 4.9,17 r0 top value=0.1uF
C80 "Capacitor NP" CAP_C_0201 5.838,-2.1 r180 top value=0.1uF
C81 "Capacitor NP" CAP_C_0201 6.4,17 r180 top value=0.1uF
C82 "Capacitor NP" CAP_C_0402 7.3,-2.2 r270 top value=4.7uF
C83 "Capacitor NP" CAP_C_0201 12.2,18.1 r0 top value=0.1uF
C84 "Capacitor NP" CAP_C_0402 8.65,-14.9 r180 top value=2.2uF
C85 "Capacitor NP" CAP_C_0201 8.838,-15.725 r180 top value=0.1uF
C86 "Capacitor NP" CAP_C_0402 10.7,-16.25 r90 top value=10uF
C87 "Capacitor NP" CAP_C_0201 11.55,-16.062 r90 top value=0.1uF
C88 "Capacitor NP" CAP_C_0402 15.85,-9.475 r180 top value=10uF
C89 "Capacitor NP" CAP_C_0201 15.662,-10.325 r180 top value=0.1uF
C90 "Capacitor NP" CAP_C_0201 15.737,-16.05 r180 top value=0.1uF
C91 "Capacitor NP" RES_C_0805 6.6,-12.05 r180 top value=47uF
C92 "Capacitor NP" CAP_C_0201 6.162,-10.8 r180 top value=0.1uF
C93 "Capacitor NP" CAP_C_0201 1.225,-18.675 r180 top value=0.1uF
C94 "Capacitor NP" CAP_C_0201 -7.713,16.825 r0 top value=0.1uF
C95 "Capacitor NP" CAP_C_0201 -6.175,8.662 r270 top value=0.1uF
C96 "Capacitor NP" CAP_C_0201 9.888,-9.05 r0 top value=0.1uF
C97 "Capacitor NP" CAP_C_0402 -13.425,2.975 r270 top value=4.7uF
C98 "Capacitor NP" CAP_C_0402 -6.275,15.1 r90 top value=4.7uF
C99 "Capacitor NP" CAP_C_0402 17.45,3.95 r270 top value=4.7uF
C100 "Capacitor NP" CAP_C_0402 12.45,18.85 r0 top value=4.7uF
C101 "Capacitor NP" CAP_C_0402 5.2,18.575 r0 top value=4.7uF
C102 "Capacitor NP" CAP_C_0201 17.4,15.425 r180 top value=100pF
C103 "Capacitor NP" CAP_C_0201 17.4,16.625 r180 top value=100pF
C104 "Capacitor NP" CAP_C_0201 -7.975,17.988 r90 top value=100pF
C105 "Capacitor NP" CAP_C_0402 5.3,-18.175 r270 top value=4.7uF
C106 "Capacitor NP" CAP_C_0201 -3.275,9.75 r270 top value=10000pF
C107 "Capacitor NP" CAP_C_0201 12.2,17.575 r0 top value=10nF
FB1 "Ferrite Bead" IND_C_0603 -15.325,2.525 r0 top value=180R
FB2 "Ferrite Bead" IND_C_0603 9.55,-17.35 r270 top value=180R
FB3 "Ferrite Bead" IND_C_0402 6.1,-13.45 r180 top value=100R
FB4 "Ferrite Bead" IND_C_0402 6.3,-18.175 r270 top value=100R
L1 "Inductor" IND_C_1008 -15.075,5.875 r180 top locked value=1.5uH
L2 "Inductor" IND_C_0603 -15.325,1.225 r0 top value=10uH
L3 "Inductor" IND_C_1008 -11.45,5.875 r0 top value=1.5uH
L4 "Inductor" IND_C_1008 -11.25,15.85 r0 top value=1.5uH
L5 "Inductor" IND_C_0603 -8.175,15.55 r0 top value=10uH
L6 "Inductor" IND_C_1008 -15.1,15.85 r180 top value=1.5uH
Q1 "Transistor MOS-N GSD" SOT-23-3 -3.55,15.2 r180 top locked value=BSS138
R1 "Resistor" RES_C_0201 -7.4,12.837 r90 top value=100k
R2 "Resistor" RES_C_0201 -8.65,13.15 r0 top value=10K
R3 "Resistor" RES_C_0201 -17.262,9.15 r0 top value=1k
R4 "Resistor" RES_C_0201 -17.175,1.95 r270 top value=2.2R
R5 "Resistor" RES_C_0201 -8.425,6.775 r270 top value=0R
R6 "Resistor" RES_C_0201 -17.288,13.425 r180 top value=10K
R8 "Resistor" RES_C_0201 -9.1,16.85 r270 top value=2.2R
R9 "Resistor" RES_C_0402 -9.35,0.575 r90 top value=1.5k
R10 "Resistor" RES_C_0402 -11.075,0.15 r0 top value=1.5k
R11 "Resistor" RES_C_0201 17.025,10.325 r90 top value=10K
R12 "Resistor" RES_C_0201 12.975,15.9 r270 top value=5.62K
R13 "Resistor" RES_C_0201 -5.15,12.35 r180 top value=2.2K
R14 "Resistor" RES_C_0201 -5.15,11.725 r180 top value=2.2K
R15 "Resistor" RES_C_0201 -5.15,11.1 r180 top value=22R
R16 "Resistor" RES_C_0201 -5.15,10.5 r180 top value=22R
R17 "Resistor" RES_C_0201 18.775,2.4 r270 top value=22R
R18 "Resistor" RES_C_0201 17.775,8.725 r0 top value=22R
R19 "Resistor" RES_C_0201 -0.8,1.425 r180 top value=240R
R20 "Resistor" RES_C_0201 10.2,-9.85 r180 top value=1k
R21 "Resistor" RES_C_0201 16.538,-12.425 r0 top value=1k
R22 "Resistor" RES_C_0201 15.525,-13 r180 top value=6.49K
R23 "Resistor" RES_C_0201 13.35,-9.5 r180 top value=10K
R24 "Resistor" RES_C_0201 10.4,-18.275 r90 top value=10K
R25 "Resistor" RES_C_0201 9,-14.05 r0 top value=0R
R26 "Resistor" RES_C_0201 -5.1,1.338 r270 top value=10K
R27 "Resistor" RES_C_0201 -3.937,17.75 r0 top value=100k
R28 "Resistor" RES_C_0201 -1,-0.95 r180 top value=68k
R29 "Resistor" RES_C_0201 -3.35,-0.313 r90 top value=68k
R30 "Resistor" RES_C_0201 6.2,-3.025 r270 top value=68k
R31 "Resistor" RES_C_0201 5.463,-3.788 r0 top value=68k
R32 "Resistor" RES_C_0201 5.2,-5.262 r270 top value=10K
R34 "Resistor" RES_C_0201 6,-9.8 r180 top value=10K
R35 "Resistor" RES_C_0201 -2.75,9.75 r270 top value=10K
R36 "Resistor" RES_C_0201 17.838,-9.1 r0 top value=10K
R37 "Resistor" RES_C_0201 9.55,-3.75 r270 top value=10K
R38 "Resistor" RES_C_0201 18.1,-8.225 r270 top value=10K
R39 "Resistor" RES_C_0201 16.8,-2.4 r270 top value=10K
R40 "Resistor" RES_C_0201 10.15,-8.138 r270 top value=10K
R41 "Resistor" RES_C_0201 9.288,-4.55 r0 top value=10K
R42 "Resistor" RES_C_0201 -4.988,9.4 r180 top value=2.2K
R43 "Resistor" RES_C_0201 -4.988,9.95 r180 top value=2.2K
R44 "Resistor" RES_C_0201 11.05,-2.95 r0 top value=22R
R45 "Resistor" RES_C_0201 18.1,-6.875 r90 top value=22R
R46 "Resistor" RES_C_0201 18.05,-5.1 r270 top value=22R
R47 "Resistor" RES_C_0201 10.15,-6.887 r90 top value=22R
R48 "Resistor" RES_C_0201 9.625,-5.412 r270 top value=22R
R49 "Resistor" RES_C_0201 9.025,-5.412 r270 top value=22R
R50 "Resistor" RES_C_0201 9.55,-7.788 r270 top value=22R
R51 "Resistor" RES_C_0201 17.55,-1.55 r0 top value=22R
R52 "Resistor" RES_C_0201 18.1,-12.125 r270 top value=22R
R53 "Resistor" RES_C_0201 10.15,-3.75 r270 top value=22R
R55 "Resistor" RES_C_0201 17.4,16.025 r180 top value=100R
R56 "Resistor" RES_C_0201 17.4,17.225 r180 top value=100R
R57 "Resistor" RES_C_0201 -8.563,18.513 r270 top value=100R
R58 "Resistor" RES_C_0201_NT -9.075,8.8 r180 top net-tie value=0R
R59 "Resistor" RES_C_0201 4.288,15.85 r180 top value=22R
R60 "Resistor" RES_C_0201 15.275,16.75 r90 top value=0R
TP1 "Test Point No BOM" TP_1mm_SMD -13.875,3 r90 bottom value="TP PAD PCB 1mm"
TP2 "Test Point No BOM" TP_1mm_SMD -15.9,3.825 r90 bottom value="TP PAD PCB 1mm"
TP3 "Test Point No BOM" TP_1mm_SMD -13.7,1.225 r90 bottom value="TP PAD PCB 1mm"
TP4 "Test Point No BOM" TP_1mm_SMD -17.975,8 r180 bottom value="TP PAD PCB 1mm"
TP6 "Test Point No BOM" TP_1mm_SMD -9.025,2.775 r90 bottom value="TP PAD PCB 1mm"
TP7 "Test Point No BOM" TP_1mm_SMD -9.5,16.825 r90 bottom value="TP PAD PCB 1mm"
TP8 "Test Point No BOM" TP_1mm_SMD -4.85,15.55 r90 bottom locked value="TP PAD PCB 1mm"
TP9 "Test Point No BOM" TP_1mm_SMD -8.875,-1.025 r180 bottom value="TP PAD PCB 1mm"
TP10 "Test Point No BOM" TP_1mm_SMD 10.825,-15.8 r180 bottom value="TP PAD PCB 1mm"
TP11 "Test Point No BOM" TP_1mm_SMD 4.35,-14.25 r0 bottom value="TP PAD PCB 1mm"
U1 "MCP16502 QFN-32" QFN-32_5X5_EP3.7X3.7 -13.1,10.9 r0 top locked value=MCP16502AC-E/S8B
U2 "SAMA5D27C-LD2G-CU" TFBGA-361-16X16 8.1,7.1 r180 top locked value=SAMA5D2-LPDDR2-SIP-BGA-361
U3 "ETHERNET QFN-24" QFN-24_4X4 12.3,-12.7 r90 top value=KSZ8081RNAIA-TR
U4 "MODULE ATWILC3000-MR110CA" "MODULE ATWILC3000-MR110CA" -4.7,-9.83 r90 top locked value=ATWILC3000-MR110UA
U5 "MIC842 TDFN-4" TDFN-4_1.6x1.2 -5.85,18 r180 top locked
U6 "ATECC608A-TNGTLSU UDFN-8" UDFN-8_2X3_EP1.5X1.3 -4.5,7 r90 top value=ATECC608A-TNGTLSU
U7 "SST26VF064B-104IMF" WSON-8_6x5_EP3.4X4.0 14.1,-5.995 r90 top locked value=SST26VF064BEUI-104I/MF
U8 "WLSOM1 188-Pins" SOM-40.8MMX40.8MM 0,0 r0 top locked
Y1 "Crystal 2 Pins" CRYSTAL_NX2012SA 17.6,12.675 r270 top value="32.768 Hz"
Y2 "OSCILLATOR 4 Pins" "DFN-4_VFLGA_1.6 X 1.2" 14.15,16.75 r270 top locked value=DSC6003HI2B-024.0000
Y3 "OSCILLATOR 4 Pins" "DFN-4_VFLGA_1.6 X 1.2" 15.85,-14.525 r90 top value=DSC6102HI2B-025.000

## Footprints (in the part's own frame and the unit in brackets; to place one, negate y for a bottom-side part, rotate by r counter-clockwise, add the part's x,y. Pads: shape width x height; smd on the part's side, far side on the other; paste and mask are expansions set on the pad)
CAP_C_0201 [mm] "Chip Capacitor, 2-Leads, Body 0.6x0.3mm, IPC Medium Density"
  rrect50% 0.275x0.3 smd mask+0.05: 1(-0.262,0) 2(0.262,0)
  body extent -0.3,-0.15 0.3,0.15, height 0.28
CAP_C_0402 [mm] "Chip Capacitor, 2-Leads, Body 1.0x0.5mm, IPC High Density"
  rrect50% 0.55x0.6 smd: 1(-0.45,0) 2(0.45,0)
  body extent -0.5,-0.3 0.5,0.3, height 0.2
CAP_C_0603 [mm] "Chip Capacitor, 2-Leads, Body 1.6x0.8mm, IPC Medium Density"
  rrect50% 0.8x0.9 smd: 1(-0.8,0) 2(0.8,0)
  silkscreen extent -0.1,-0.38 0.1,0.38, body extent -0.8,-0.4 0.8,0.4, height 0.3
CRYSTAL_NX2012SA [mil] "Crystal NDK NX2012SA"
  rect 40x50 smd paste-1: 1(-30,0) 2(30,0)
  silkscreen extent -64,-39 64,39, body extent -40,-20 40,20, height 21
"DFN-4_VFLGA_1.6 X 1.2" [mm] "DFN, 4-Leads, Body 1.60x1.20mm, Pitch 1.25mm, IPC Medium Density"
  rect 0.43x0.5 smd: 1(-0.56,-0.375)
  rect 0.35x0.5 smd: 2(0.6,-0.375) 3(0.6,0.375) 4(-0.6,0.375)
  silkscreen extent -0.9,-0.78 0.9,0.79, body extent -0.8,-0.6 0.8,0.6, height 0.61
IND_C_0402 [mm]
  rrect50% 0.55x0.6 smd: 1(-0.45,0) 2(0.45,0)
  body extent -0.5,-0.3 0.5,0.3, height 0.49
IND_C_0603 [mm] "Chip Inductor, 2-Leads, Body 1.6x0.8mm, IPC Medium Density"
  rrect50% 0.8x0.9 smd: 1(-0.8,0) 2(0.8,0)
  silkscreen extent -0.1,-0.35 0.1,0.35, body extent -0.8,-0.4 0.8,0.4, height 0.95
IND_C_1008 [mm]
  rect 0.9x2.4 smd mask+0.075: 1(-1,0) 2(1,0)
  silkscreen extent -0.25,-1.1 0.25,1.1, body extent -1.24,-1 1.26,1, height 1.2
"MODULE ATWILC3000-MR110CA" [mm]
  rect 1.88x0.813 smd: 1(-7.31,8.05) 2(-7.31,6.85) 3(-7.31,5.65) 4(-7.31,4.45) 5(-7.31,3.25) 6(-7.31,2.05) 7(-7.31,0.85) 8(-7.31,-0.35) 9(-7.31,-1.55) 10(-7.31,-2.75) 11(-7.31,-3.95) 12(-7.31,-5.15) 13(-7.31,-6.35) 25(7.37,-6.35) 26(7.37,-5.15) 27(7.37,-3.95) 28(7.37,-2.75) 29(7.37,-1.55) 30(7.37,-0.35) 31(7.37,0.85) 32(7.37,2.05) 33(7.37,3.25) 34(7.37,4.45) 35(7.37,5.65) 36(7.37,6.85)
  rect 0.813x1.88 smd: 14(-5.97,-8.33) 15(-4.77,-8.33) 16(-3.57,-8.33) 17(-2.37,-8.33) 18(-1.17,-8.33) 19(0.03,-8.33) 20(1.23,-8.33) 21(2.43,-8.33) 22(3.63,-8.33) 23(4.83,-8.33) 24(6.03,-8.33)
  rect 4.6x4.6 smd paste-5: 37(0,0)
  silkscreen extent -7.75,-8.75 7.75,14.25, body extent -7.31,-8.33 7.37,14.05, height 2.73
QFN-24_4X4 [mm]
  oval 0.85x0.3 smd mask+0.05: 1(-1.95,1.25) 2(-1.95,0.75) 3(-1.95,0.25) 4(-1.95,-0.25) 5(-1.95,-0.75) 6(-1.95,-1.25) 13(1.95,-1.25) 14(1.95,-0.75) 15(1.95,-0.25) 16(1.95,0.25) 17(1.95,0.75) 18(1.95,1.25)
  oval 0.3x0.85 smd mask+0.05: 7(-1.25,-1.95) 8(-0.75,-1.95) 9(-0.25,-1.95) 10(0.25,-1.95) 11(0.75,-1.95) 12(1.25,-1.95) 19(1.25,1.95) 20(0.75,1.95) 21(0.25,1.95) 22(-0.25,1.95) 23(-0.75,1.95) 24(-1.25,1.95)
  rect 2.5x2.5 smd paste-0.33 mask+0.05: 25(0,0)
  silkscreen extent -2.15,-2.15 2.15,2.15, body extent -2,-2 2,2, height 0.9
QFN-32_5X5_EP3.7X3.7 [mm] "QFN32_5MMwith ePAD"
  rrect50% 0.7x0.3 smd mask+0.05: 1(-2.5,1.75) 2(-2.5,1.25) 3(-2.5,0.75) 4(-2.5,0.25) 5(-2.5,-0.25) 6(-2.5,-0.75) 7(-2.5,-1.25) 8(-2.5,-1.75) 17(2.5,-1.75) 18(2.5,-1.25) 19(2.5,-0.75) 20(2.5,-0.25) 21(2.5,0.25) 22(2.5,0.75) 23(2.5,1.25) 24(2.5,1.75)
  rrect50% 0.3x0.7 smd mask+0.05: 9(-1.75,-2.5) 10(-1.25,-2.5) 11(-0.75,-2.5) 12(-0.25,-2.5) 13(0.25,-2.5) 14(0.75,-2.5) 15(1.25,-2.5) 16(1.75,-2.5) 25(1.75,2.5) 26(1.25,2.5) 27(0.75,2.5) 28(0.25,2.5) 29(-0.25,2.5) 30(-0.75,2.5) 31(-1.25,2.5) 32(-1.75,2.5)
  rect 3.7x3.7 smd mask+0.05: 33(0,0)
  silkscreen extent -2.65,-2.65 2.65,2.68, body extent -2.56,-2.56 2.56,2.56, height 1.01
RES_C_0201 [mm] "Chip Resistor, 2-Leads, Body 0.6x0.3mm, IPC Medium Density"
  rrect50% 0.275x0.3 smd mask+0.05: 1(-0.262,0) 2(0.262,0)
  body extent -0.3,-0.15 0.3,0.15, height 0.22
RES_C_0201_NT [mm] "Chip Resistor, 2-Leads, Body 0.6x0.3mm, IPC Medium Density"
  rrect50% 0.275x0.3 smd mask+0.05: 1(-0.262,0) 2(0.262,0)
  L1 - Top lines w0.2: 0.262,0 -0.262,0
  body extent -0.3,-0.15 0.3,0.15, height 0.22
RES_C_0402 [mm] "Chip Resistor, 2-Leads, Body 1.0x0.5mm, IPC Medium Density"
  rrect50% 0.55x0.6 smd: 1(-0.45,0) 2(0.45,0)
  body extent -0.5,-0.3 0.5,0.3, height 0.2
RES_C_0805 [mm] "Chip Resistor, 2-Leads, Body 2.0x1.3mm, IPC Medium Density"
  rrect50% 0.9x1.4 smd: 1(-0.95,0) 2(0.95,0)
  silkscreen extent -0.2,-0.7 0.2,0.7, body extent -1,-0.63 1,0.63, height 0.78
SOM-40.8MMX40.8MM [mm] "188-Castellated thru-holes"
  rect 1.6x0.6 / inner rect 1.6x0.6 / far side rect 3x0.6 hole 0.4 mask+0.05: 1(-20.4,18.4) 2(-20.4,17.6) 3(-20.4,16.8) 4(-20.4,16) 5(-20.4,15.2) 6(-20.4,14.4) 7(-20.4,13.6) 8(-20.4,12.8) 9(-20.4,12) 10(-20.4,11.2) 11(-20.4,10.4) 12(-20.4,9.6) 13(-20.4,8.8) 14(-20.4,8) 15(-20.4,7.2) 16(-20.4,6.4) 17(-20.4,5.6) 18(-20.4,4.8) 19(-20.4,4) 20(-20.4,3.2) 21(-20.4,2.4) 22(-20.4,1.6) 23(-20.4,0.8) 24(-20.4,0) 25(-20.4,-0.8) 26(-20.4,-1.6) 27(-20.4,-2.4) 28(-20.4,-3.2) 29(-20.4,-4) 30(-20.4,-4.8) 31(-20.4,-5.6) 32(-20.4,-6.4) 33(-20.4,-7.2) 34(-20.4,-8) 35(-20.4,-8.8) 36(-20.4,-9.6) 37(-20.4,-10.4) 38(-20.4,-11.2) 39(-20.4,-12) 40(-20.4,-12.8) 41(-20.4,-13.6) 42(-20.4,-14.4) 43(-20.4,-15.2) 44(-20.4,-16) 45(-20.4,-16.8) 46(-20.4,-17.6) 47(-20.4,-18.4) 95(20.4,-18.4) 96(20.4,-17.6) 97(20.4,-16.8) 98(20.4,-16) 99(20.4,-15.2) 100(20.4,-14.4) 101(20.4,-13.6) 102(20.4,-12.8) 103(20.4,-12) 104(20.4,-11.2) 105(20.4,-10.4) 106(20.4,-9.6) 107(20.4,-8.8) 108(20.4,-8) 109(20.4,-7.2) 110(20.4,-6.4) 111(20.4,-5.6) 112(20.4,-4.8) 113(20.4,-4) 114(20.4,-3.2) 115(20.4,-2.4) 116(20.4,-1.6) 117(20.4,-0.8) 118(20.4,0) 119(20.4,0.8) 120(20.4,1.6) 121(20.4,2.4) 122(20.4,3.2) 123(20.4,4) 124(20.4,4.8) 125(20.4,5.6) 126(20.4,6.4) 127(20.4,7.2) 128(20.4,8) 129(20.4,8.8) 130(20.4,9.6) 131(20.4,10.4) 132(20.4,11.2) 133(20.4,12) 134(20.4,12.8) 135(20.4,13.6) 136(20.4,14.4) 137(20.4,15.2) 138(20.4,16) 139(20.4,16.8) 140(20.4,17.6) 141(20.4,18.4)
  rect 0.6x1.6 / inner rect 0.6x1.6 / far side rect 0.6x3 hole 0.4 mask+0.05: 48(-18.4,-20.4) 49(-17.6,-20.4) 50(-16.8,-20.4) 51(-16,-20.4) 52(-15.2,-20.4) 53(-14.4,-20.4) 54(-13.6,-20.4) 55(-12.8,-20.4) 56(-12,-20.4) 57(-11.2,-20.4) 58(-10.4,-20.4) 59(-9.6,-20.4) 60(-8.8,-20.4) 61(-8,-20.4) 62(-7.2,-20.4) 63(-6.4,-20.4) 64(-5.6,-20.4) 65(-4.8,-20.4) 66(-4,-20.4) 67(-3.2,-20.4) 68(-2.4,-20.4) 69(-1.6,-20.4) 70(-0.8,-20.4) 71(0,-20.4) 72(0.8,-20.4) 73(1.6,-20.4) 74(2.4,-20.4) 75(3.2,-20.4) 76(4,-20.4) 77(4.8,-20.4) 78(5.6,-20.4) 79(6.4,-20.4) 80(7.2,-20.4) 81(8,-20.4) 82(8.8,-20.4) 83(9.6,-20.4) 84(10.4,-20.4) 85(11.2,-20.4) 86(12,-20.4) 87(12.8,-20.4) 88(13.6,-20.4) 89(14.4,-20.4) 90(15.2,-20.4) 91(16,-20.4) 92(16.8,-20.4) 93(17.6,-20.4) 94(18.4,-20.4) 142(18.4,20.4) 143(17.6,20.4) 144(16.8,20.4) 145(16,20.4) 146(15.2,20.4) 147(14.4,20.4) 148(13.6,20.4) 149(12.8,20.4) 150(12,20.4) 151(11.2,20.4) 152(10.4,20.4) 153(9.6,20.4) 154(8.8,20.4) 155(8,20.4) 156(7.2,20.4) 157(6.4,20.4) 158(5.6,20.4) 159(4.8,20.4) 160(4,20.4) 161(3.2,20.4) 162(2.4,20.4) 163(1.6,20.4) 164(0.8,20.4) 165(0,20.4) 166(-0.8,20.4) 167(-1.6,20.4) 168(-2.4,20.4) 169(-3.2,20.4) 170(-4,20.4) 171(-4.8,20.4) 172(-5.6,20.4) 173(-6.4,20.4) 174(-7.2,20.4) 175(-8,20.4) 176(-8.8,20.4) 177(-9.6,20.4) 178(-10.4,20.4) 179(-11.2,20.4) 180(-12,20.4) 181(-12.8,20.4) 182(-13.6,20.4) 183(-14.4,20.4) 184(-15.2,20.4) 185(-16,20.4) 186(-16.8,20.4) 187(-17.6,20.4) 188(-18.4,20.4)
  silkscreen extent -20.4,19.4 -19.4,20.4, body extent -20.4,-20.4 20.4,20.4, height 0.04
SOT-23-3 [mm]
  rect 0.65x1.05 smd: 1(-0.95,-1.15) 2(0.95,-1.15) 3(0,1.15)
  silkscreen extent -1.6,-0.75 1.6,0.72, body extent -1.5,-1.25 1.5,1.25, height 1.09
TDFN-4_1.6x1.2 [mm]
  rect 0.5x0.25 smd paste+0 mask+0.05: 1(-0.7,0.25) 2(-0.7,-0.25) 3(0.7,-0.25) 4(0.7,0.25)
  rect 0.5x0.86 smd paste-0.1 mask+0.05: EP(0,0)
  silkscreen extent -0.8,-0.7 0.8,0.67, body extent -0.8,-0.6 0.81,0.6, height 0.5
TFBGA-361-16X16 [mm] "361-Ball TFBGA, 16.00mm x 16.00mm, pitch 0.80mm"
  round 0.4 smd mask+0.05: A1(-7.2,7.2) A2(-6.4,7.2) A3(-5.6,7.2) A4(-4.8,7.2) A5(-4,7.2) A6(-3.2,7.2) A7(-2.4,7.2) A8(-1.6,7.2) A9(-0.8,7.2) A10(0,7.2) A11(0.8,7.2) A12(1.6,7.2) A13(2.4,7.2) A14(3.2,7.2) A15(4,7.2) A16(4.8,7.2) A17(5.6,7.2) A18(6.4,7.2) A19(7.2,7.2) B1(-7.2,6.4) B2(-6.4,6.4) B3(-5.6,6.4) B4(-4.8,6.4) B5(-4,6.4) B6(-3.2,6.4) B7(-2.4,6.4) B8(-1.6,6.4) B9(-0.8,6.4) B10(0,6.4) B11(0.8,6.4) B12(1.6,6.4) B13(2.4,6.4) B14(3.2,6.4) B15(4,6.4) B16(4.8,6.4) B17(5.6,6.4) B18(6.4,6.4) B19(7.2,6.4) C1(-7.2,5.6) C2(-6.4,5.6) C3(-5.6,5.6) C4(-4.8,5.6) C5(-4,5.6) C6(-3.2,5.6) C7(-2.4,5.6) C8(-1.6,5.6) C9(-0.8,5.6) C10(0,5.6) C11(0.8,5.6) C12(1.6,5.6) C13(2.4,5.6) C14(3.2,5.6) C15(4,5.6) C16(4.8,5.6) C17(5.6,5.6) C18(6.4,5.6) C19(7.2,5.6) D1(-7.2,4.8) D2(-6.4,4.8) D3(-5.6,4.8) D4(-4.8,4.8) D5(-4,4.8) D6(-3.2,4.8) D7(-2.4,4.8) D8(-1.6,4.8) D9(-0.8,4.8) D10(0,4.8) D11(0.8,4.8) D12(1.6,4.8) D13(2.4,4.8) D14(3.2,4.8) D15(4,4.8) D16(4.8,4.8) D17(5.6,4.8) D18(6.4,4.8) D19(7.2,4.8) E1(-7.2,4) E2(-6.4,4) E3(-5.6,4) E4(-4.8,4) E5(-4,4) E6(-3.2,4) E7(-2.4,4) E8(-1.6,4) E9(-0.8,4) E10(0,4) E11(0.8,4) E12(1.6,4) E13(2.4,4) E14(3.2,4) E15(4,4) E16(4.8,4) E17(5.6,4) E18(6.4,4) E19(7.2,4) F1(-7.2,3.2) F2(-6.4,3.2) F3(-5.6,3.2) F4(-4.8,3.2) F5(-4,3.2) F6(-3.2,3.2) F7(-2.4,3.2) F8(-1.6,3.2) F9(-0.8,3.2) F10(0,3.2) F11(0.8,3.2) F12(1.6,3.2) F13(2.4,3.2) F14(3.2,3.2) F15(4,3.2) F16(4.8,3.2) F17(5.6,3.2) F18(6.4,3.2) F19(7.2,3.2) G1(-7.2,2.4) G2(-6.4,2.4) G3(-5.6,2.4) G4(-4.8,2.4) G5(-4,2.4) G6(-3.2,2.4) G7(-2.4,2.4) G8(-1.6,2.4) G9(-0.8,2.4) G10(0,2.4) G11(0.8,2.4) G12(1.6,2.4) G13(2.4,2.4) G14(3.2,2.4) G15(4,2.4) G16(4.8,2.4) G17(5.6,2.4) G18(6.4,2.4) G19(7.2,2.4) H1(-7.2,1.6) H2(-6.4,1.6) H3(-5.6,1.6) H4(-4.8,1.6) H5(-4,1.6) H6(-3.2,1.6) H7(-2.4,1.6) H8(-1.6,1.6) H9(-0.8,1.6) H10(0,1.6) H11(0.8,1.6) H12(1.6,1.6) H13(2.4,1.6) H14(3.2,1.6) H15(4,1.6) H16(4.8,1.6) H17(5.6,1.6) H18(6.4,1.6) H19(7.2,1.6) J1(-7.2,0.8) J2(-6.4,0.8) J3(-5.6,0.8) J4(-4.8,0.8) J5(-4,0.8) J6(-3.2,0.8) J7(-2.4,0.8) J8(-1.6,0.8) J9(-0.8,0.8) J10(0,0.8) J11(0.8,0.8) J12(1.6,0.8) J13(2.4,0.8) J14(3.2,0.8) J15(4,0.8) J16(4.8,0.8) J17(5.6,0.8) J18(6.4,0.8) J19(7.2,0.8) K1(-7.2,0) K2(-6.4,0) K3(-5.6,0) K4(-4.8,0) K5(-4,0) K6(-3.2,0) K7(-2.4,0) K8(-1.6,0) K9(-0.8,0) K10(0,0) K11(0.8,0) K12(1.6,0) K13(2.4,0) K14(3.2,0) K15(4,0) K16(4.8,0) K17(5.6,0) K18(6.4,0) K19(7.2,0) L1(-7.2,-0.8) L2(-6.4,-0.8) L3(-5.6,-0.8) L4(-4.8,-0.8) L5(-4,-0.8) L6(-3.2,-0.8) L7(-2.4,-0.8) L8(-1.6,-0.8) L9(-0.8,-0.8) L10(0,-0.8) L11(0.8,-0.8) L12(1.6,-0.8) L13(2.4,-0.8) L14(3.2,-0.8) L15(4,-0.8) L16(4.8,-0.8) L17(5.6,-0.8) L18(6.4,-0.8) L19(7.2,-0.8) M1(-7.2,-1.6) M2(-6.4,-1.6) M3(-5.6,-1.6) M4(-4.8,-1.6) M5(-4,-1.6) M6(-3.2,-1.6) M7(-2.4,-1.6) M8(-1.6,-1.6) M9(-0.8,-1.6) M10(0,-1.6) M11(0.8,-1.6) M12(1.6,-1.6) M13(2.4,-1.6) M14(3.2,-1.6) M15(4,-1.6) M16(4.8,-1.6) M17(5.6,-1.6) M18(6.4,-1.6) M19(7.2,-1.6) N1(-7.2,-2.4) N2(-6.4,-2.4) N3(-5.6,-2.4) N4(-4.8,-2.4) N5(-4,-2.4) N6(-3.2,-2.4) N7(-2.4,-2.4) N8(-1.6,-2.4) N9(-0.8,-2.4) N10(0,-2.4) N11(0.8,-2.4) N12(1.6,-2.4) N13(2.4,-2.4) N14(3.2,-2.4) N15(4,-2.4) N16(4.8,-2.4) N17(5.6,-2.4) N18(6.4,-2.4) N19(7.2,-2.4) P1(-7.2,-3.2) P2(-6.4,-3.2) P3(-5.6,-3.2) P4(-4.8,-3.2) P5(-4,-3.2) P6(-3.2,-3.2) P7(-2.4,-3.2) P8(-1.6,-3.2) P9(-0.8,-3.2) P10(0,-3.2) P11(0.8,-3.2) P12(1.6,-3.2) P13(2.4,-3.2) P14(3.2,-3.2) P15(4,-3.2) P16(4.8,-3.2) P17(5.6,-3.2) P18(6.4,-3.2) P19(7.2,-3.2) R1(-7.2,-4) R2(-6.4,-4) R3(-5.6,-4) R4(-4.8,-4) R5(-4,-4) R6(-3.2,-4) R7(-2.4,-4) R8(-1.6,-4) R9(-0.8,-4) R10(0,-4) R11(0.8,-4) R12(1.6,-4) R13(2.4,-4) R14(3.2,-4) R15(4,-4) R16(4.8,-4) R17(5.6,-4) R18(6.4,-4) R19(7.2,-4) T1(-7.2,-4.8) T2(-6.4,-4.8) T3(-5.6,-4.8) T4(-4.8,-4.8) T5(-4,-4.8) T6(-3.2,-4.8) T7(-2.4,-4.8) T8(-1.6,-4.8) T9(-0.8,-4.8) T10(0,-4.8) T11(0.8,-4.8) T12(1.6,-4.8) T13(2.4,-4.8) T14(3.2,-4.8) T15(4,-4.8) T16(4.8,-4.8) T17(5.6,-4.8) T18(6.4,-4.8) T19(7.2,-4.8) U1(-7.2,-5.6) U2(-6.4,-5.6) U3(-5.6,-5.6) U4(-4.8,-5.6) U5(-4,-5.6) U6(-3.2,-5.6) U7(-2.4,-5.6) U8(-1.6,-5.6) U9(-0.8,-5.6) U10(0,-5.6) U11(0.8,-5.6) U12(1.6,-5.6) U13(2.4,-5.6) U14(3.2,-5.6) U15(4,-5.6) U16(4.8,-5.6) U17(5.6,-5.6) U18(6.4,-5.6) U19(7.2,-5.6) V1(-7.2,-6.4) V2(-6.4,-6.4) V3(-5.6,-6.4) V4(-4.8,-6.4) V5(-4,-6.4) V6(-3.2,-6.4) V7(-2.4,-6.4) V8(-1.6,-6.4) V9(-0.8,-6.4) V10(0,-6.4) V11(0.8,-6.4) V12(1.6,-6.4) V13(2.4,-6.4) V14(3.2,-6.4) V15(4,-6.4) V16(4.8,-6.4) V17(5.6,-6.4) V18(6.4,-6.4) V19(7.2,-6.4) W1(-7.2,-7.2) W2(-6.4,-7.2) W3(-5.6,-7.2) W4(-4.8,-7.2) W5(-4,-7.2) W6(-3.2,-7.2) W7(-2.4,-7.2) W8(-1.6,-7.2) W9(-0.8,-7.2) W10(0,-7.2) W11(0.8,-7.2) W12(1.6,-7.2) W13(2.4,-7.2) W14(3.2,-7.2) W15(4,-7.2) W16(4.8,-7.2) W17(5.6,-7.2) W18(6.4,-7.2) W19(7.2,-7.2)
  silkscreen extent -8.25,-8.25 8.25,8.25, body extent -8,-8 8,8, height 1.2
TP_1mm_SMD [mm]
  round 1 smd paste-1: 1(0,0)
UDFN-8_2X3_EP1.5X1.3 [mm] "PQFN, 8-Leads, Body 3.00x2.00mm, Pitch 0.50mm, Thermal Pad 1.30x1.50mm, IPC Medium Density"
  rect 0.5x0.3 smd paste-0.046 mask+0.05: 1(-1.398,0.75) 2(-1.398,0.25) 3(-1.398,-0.25) 4(-1.398,-0.75) 5(1.398,-0.75) 6(1.398,-0.25) 7(1.398,0.25) 8(1.398,0.75)
  rect 1.3x1.5 smd paste-0.076: 9(0,0)
  body extent -1.55,-1.05 1.55,1.05, height 0.64
WSON-8_6x5_EP3.4X4.0 [mm]
  rect 0.45x1.1 smd: 1(-1.905,-2.8) 2(-0.635,-2.8) 3(0.635,-2.8) 4(1.905,-2.8) 5(1.905,2.8) 6(0.635,2.8) 7(-0.635,2.8) 8(-1.905,2.8)
  rect 4x3.4 smd paste-0.3: 9(0,0)
  silkscreen extent -2.6,-3.1 2.6,3.1, body extent -2.5,-3 2.5,3, height 0.85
